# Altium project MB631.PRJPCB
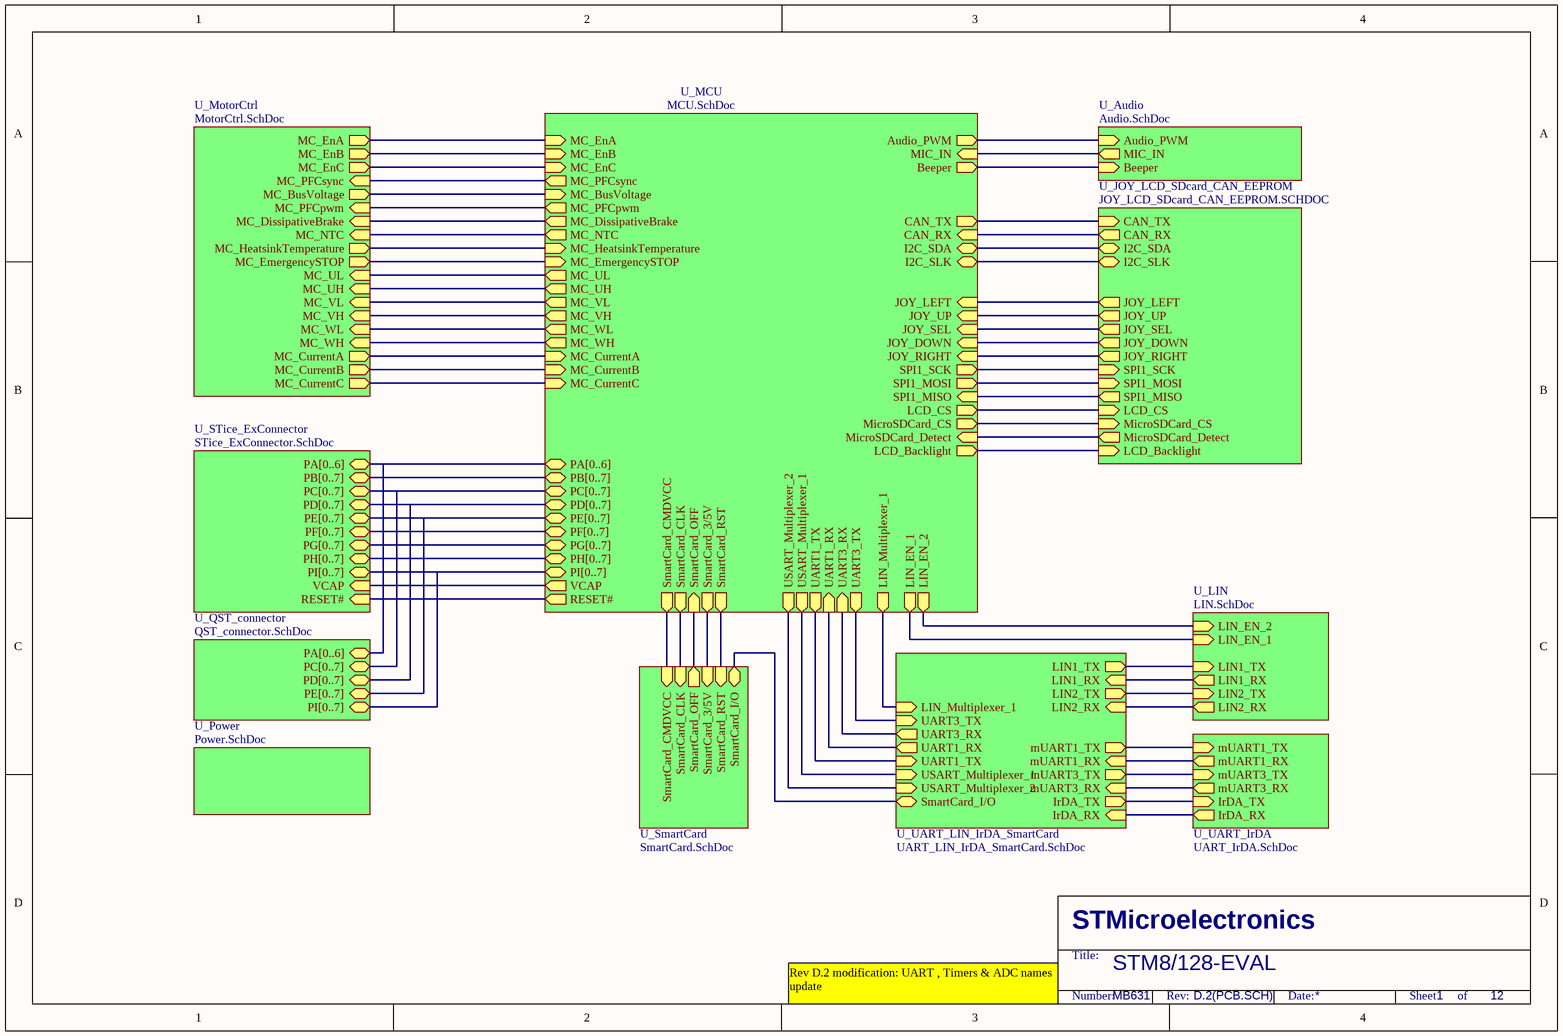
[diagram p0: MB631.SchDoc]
12 sheets, 273 parts. Net scope: hierarchical (ports join the sheet entries above them; power ports are global).
Board file: MB631.PCBDOC
Sheets:
  MB631.SchDoc
    U_MCU = MCU.SchDoc
    U_Audio = Audio.SchDoc
    U_MotorCtrl = MotorCtrl.SchDoc
    U_JOY_LCD_SDcard_CAN_EEPROM = JOY_LCD_SDcard_CAN_EEPROM.SCHDOC
    U_Power = Power.SchDoc
    U_STice_ExConnector = STice_ExConnector.SchDoc
    U_QST_connector = QST_connector.SchDoc
    U_LIN = LIN.SchDoc
    U_UART_IrDA = UART_IrDA.SchDoc
    U_UART_LIN_IrDA_SmartCard = UART_LIN_IrDA_SmartCard.SchDoc
    U_SmartCard = SmartCard.SchDoc

## Sheet MB631.SchDoc
size A4; Revision: D.2(PCB.SCH)

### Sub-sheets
U_Audio = Audio.SchDoc: Audio_PWM (in), MIC_IN (out), Beeper (in)
U_JOY_LCD_SDcard_CAN_EEPROM = JOY_LCD_SDcard_CAN_EEPROM.SCHDOC: JOY_SEL (out), JOY_DOWN (out), JOY_LEFT (out), JOY_RIGHT (out), JOY_UP (out), CAN_TX (in), CAN_RX (out), SPI1_SCK (in), SPI1_MISO (out), SPI1_MOSI (in), MicroSDCard_CS (in), LCD_CS (in), I2C_SLK (bidir), I2C_SDA (bidir), MicroSDCard_Detect (out), LCD_Backlight (in)
U_LIN = LIN.SchDoc: LIN_EN_1 (in), LIN1_TX (in), LIN1_RX (out), LIN_EN_2 (in), LIN2_TX (in), LIN2_RX (out)
U_MCU = MCU.SchDoc: MC_EnA (in), MC_EnB (in), MC_BusVoltage (in), SPI1_SCK (out), SPI1_MISO (in), SPI1_MOSI (out), MC_PFCsync (out), MC_PFCpwm (out), Audio_PWM (out), SmartCard_RST (out), SmartCard_CLK (out), MC_EnC (in), JOY_DOWN (in), MC_DissipativeBrake (out), JOY_SEL (in), SmartCard_3/5V (out), MC_NTC (out), JOY_UP (in), CAN_TX (out), CAN_RX (in), MC_EmergencySTOP (in), SmartCard_OFF (in), MC_WL (out), MC_VH (out), MC_VL (out), MC_UH (out), MC_UL (out), SmartCard_CMDVCC (out), JOY_LEFT (in), JOY_RIGHT (in), MC_WH (out), LCD_CS (out), MicroSDCard_CS (out), MC_CurrentC (in), MC_CurrentB (in), MC_CurrentA (in), MC_HeatsinkTemperature (in), MIC_IN (in), UART1_TX (out), UART1_RX (in), UART3_TX (out), UART3_RX (in), I2C_SLK (bidir), I2C_SDA (bidir), USART_Multiplexer_1 (out), USART_Multiplexer_2 (out), LIN_Multiplexer_1 (out), LIN_EN_1 (out), LIN_EN_2 (out), MicroSDCard_Detect (in), LCD_Backlight (out), Beeper (out), PA[0..6] (bidir), PB[0..7] (bidir), PC[0..7] (bidir), PD[0..7] (bidir), PE[0..7] (bidir), PF[0..7] (bidir), PG[0..7] (bidir), PH[0..7] (bidir), PI[0..7] (bidir), VCAP (out), RESET# (out)
U_MotorCtrl = MotorCtrl.SchDoc: MC_EmergencySTOP (out), MC_CurrentA (out), MC_CurrentB (out), MC_CurrentC (out), MC_PFCsync (in), MC_WL (in), MC_VH (in), MC_VL (in), MC_UH (in), MC_UL (in), MC_WH (in), MC_NTC (in), MC_DissipativeBrake (in), MC_PFCpwm (in), MC_EnA (out), MC_EnB (out), MC_HeatsinkTemperature (out), MC_BusVoltage (out), MC_EnC (out)
U_Power = Power.SchDoc: no entries
U_QST_connector = QST_connector.SchDoc: PA[0..6] (bidir), PC[0..7] (bidir), PD[0..7] (bidir), PE[0..7] (bidir), PI[0..7] (bidir)
U_SmartCard = SmartCard.SchDoc: SmartCard_3/5V (in), SmartCard_RST (in), SmartCard_CLK (in), SmartCard_OFF (out), SmartCard_CMDVCC (in), SmartCard_I/O (bidir)
U_STice_ExConnector = STice_ExConnector.SchDoc: PA[0..6] (bidir), PB[0..7] (bidir), PC[0..7] (bidir), PD[0..7] (bidir), PE[0..7] (bidir), PF[0..7] (bidir), PG[0..7] (bidir), PH[0..7] (bidir), PI[0..7] (bidir), VCAP (in), RESET# (in)
U_UART_IrDA = UART_IrDA.SchDoc: IrDA_TX (in), IrDA_RX (out), mUART1_TX (in), mUART1_RX (out), mUART3_TX (in), mUART3_RX (out)
U_UART_LIN_IrDA_SmartCard = UART_LIN_IrDA_SmartCard.SchDoc: USART_Multiplexer_1 (in), USART_Multiplexer_2 (in), LIN_Multiplexer_1 (in), UART1_TX (in), UART1_RX (out), UART3_TX (in), UART3_RX (out), LIN1_TX (out), LIN1_RX (in), IrDA_TX (out), IrDA_RX (in), SmartCard_I/O (bidir), mUART1_TX (out), mUART1_RX (in), LIN2_TX (out), LIN2_RX (in), mUART3_TX (out), mUART3_RX (in)

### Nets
PA3: sheet U_MCU/MC_EnC, sheet U_MotorCtrl/MC_EnC
PA4: sheet U_MCU/UART1_RX, sheet U_UART_LIN_IrDA_SmartCard/UART1_RX
PA5: sheet U_MCU/UART1_TX, sheet U_UART_LIN_IrDA_SmartCard/UART1_TX
PA6: sheet U_MCU/SmartCard_CLK, sheet U_SmartCard/SmartCard_CLK
PB0: sheet U_MCU/MC_CurrentC, sheet U_MotorCtrl/MC_CurrentC
PB1: sheet U_MCU/MC_CurrentB, sheet U_MotorCtrl/MC_CurrentB
PB2: sheet U_MCU/MC_CurrentA, sheet U_MotorCtrl/MC_CurrentA
PB3: sheet U_MCU/MC_BusVoltage, sheet U_MotorCtrl/MC_BusVoltage
PB4: sheet U_MCU/JOY_LEFT, sheet U_JOY_LCD_SDcard_CAN_EEPROM/JOY_LEFT
PB5: sheet U_MCU/JOY_RIGHT, sheet U_JOY_LCD_SDcard_CAN_EEPROM/JOY_RIGHT
PB6: sheet U_MCU/JOY_UP, sheet U_JOY_LCD_SDcard_CAN_EEPROM/JOY_UP
PB7: sheet U_MCU/JOY_DOWN, sheet U_JOY_LCD_SDcard_CAN_EEPROM/JOY_DOWN
PC1: sheet U_MCU/MC_UH, sheet U_MotorCtrl/MC_UH
PC2: sheet U_MCU/MC_VH, sheet U_MotorCtrl/MC_VH
PC3: sheet U_MCU/MC_WH, sheet U_MotorCtrl/MC_WH
PC4: sheet U_MCU/Audio_PWM, sheet U_Audio/Audio_PWM
PC5: sheet U_MCU/SPI1_SCK, sheet U_JOY_LCD_SDcard_CAN_EEPROM/SPI1_SCK
PC6: sheet U_MCU/SPI1_MOSI, sheet U_JOY_LCD_SDcard_CAN_EEPROM/SPI1_MOSI
PC7: sheet U_MCU/SPI1_MISO, sheet U_JOY_LCD_SDcard_CAN_EEPROM/SPI1_MISO
PD2: sheet U_MCU/MC_PFCsync, sheet U_MotorCtrl/MC_PFCsync
PD3: sheet U_MCU/MC_EnA, sheet U_MotorCtrl/MC_EnA
PD4: sheet U_MCU/MC_EnB, sheet U_MCU/Beeper, sheet U_Audio/Beeper, sheet U_MotorCtrl/MC_EnB
PD5: sheet U_MCU/UART3_TX, sheet U_UART_LIN_IrDA_SmartCard/UART3_TX
PD6: sheet U_MCU/UART3_RX, sheet U_UART_LIN_IrDA_SmartCard/UART3_RX
PD7: sheet U_MCU/JOY_SEL, sheet U_JOY_LCD_SDcard_CAN_EEPROM/JOY_SEL
PE0: sheet U_MCU/SmartCard_OFF, sheet U_SmartCard/SmartCard_OFF
PE1: sheet U_MCU/I2C_SLK, sheet U_JOY_LCD_SDcard_CAN_EEPROM/I2C_SLK
PE2: sheet U_MCU/I2C_SDA, sheet U_JOY_LCD_SDcard_CAN_EEPROM/I2C_SDA
PE3: sheet U_MCU/MC_EmergencySTOP, sheet U_MotorCtrl/MC_EmergencySTOP
PE5: sheet U_MCU/MicroSDCard_CS, sheet U_JOY_LCD_SDcard_CAN_EEPROM/MicroSDCard_CS
PE7: sheet U_MCU/MC_HeatsinkTemperature, sheet U_MotorCtrl/MC_HeatsinkTemperature
PF0: sheet U_MCU/LCD_CS, sheet U_JOY_LCD_SDcard_CAN_EEPROM/LCD_CS
PF3: sheet U_MCU/MIC_IN, sheet U_Audio/MIC_IN
PF5: sheet U_MCU/USART_Multiplexer_1, sheet U_UART_LIN_IrDA_SmartCard/USART_Multiplexer_1
PF6: sheet U_MCU/USART_Multiplexer_2, sheet U_UART_LIN_IrDA_SmartCard/USART_Multiplexer_2
PF7: sheet U_MCU/LIN_EN_1, sheet U_LIN/LIN_EN_1
PG0: sheet U_MCU/CAN_TX, sheet U_JOY_LCD_SDcard_CAN_EEPROM/CAN_TX
PG1: sheet U_MCU/CAN_RX, sheet U_JOY_LCD_SDcard_CAN_EEPROM/CAN_RX
PG2: sheet U_MCU/MC_NTC, sheet U_MotorCtrl/MC_NTC
PG3: sheet U_MCU/LIN_EN_2, sheet U_LIN/LIN_EN_2
PG4: sheet U_MCU/SmartCard_3/5V, sheet U_SmartCard/SmartCard_3/5V
PG5: sheet U_MCU/SmartCard_RST, sheet U_SmartCard/SmartCard_RST
PG6: sheet U_MCU/LIN_Multiplexer_1, sheet U_UART_LIN_IrDA_SmartCard/LIN_Multiplexer_1
PG7: sheet U_MCU/SmartCard_CMDVCC, sheet U_SmartCard/SmartCard_CMDVCC
PH4: sheet U_MCU/LCD_Backlight, sheet U_JOY_LCD_SDcard_CAN_EEPROM/LCD_Backlight
PH5: sheet U_MCU/MC_WL, sheet U_MotorCtrl/MC_WL
PH6: sheet U_MCU/MC_VL, sheet U_MotorCtrl/MC_VL
PH7: sheet U_MCU/MC_UL, sheet U_MotorCtrl/MC_UL
RESET#: sheet U_MCU/RESET#, sheet U_STice_ExConnector/RESET#
VCAP: sheet U_MCU/VCAP, sheet U_STice_ExConnector/VCAP
NetC39_2: sheet U_MCU/MC_PFCpwm, sheet U_MotorCtrl/MC_PFCpwm
NetCN9_10: sheet U_MCU/MicroSDCard_Detect, sheet U_JOY_LCD_SDcard_CAN_EEPROM/MicroSDCard_Detect
NetCN10_23: sheet U_MCU/MC_DissipativeBrake, sheet U_MotorCtrl/MC_DissipativeBrake
NetU14_3: sheet U_UART_IrDA/IrDA_TX, sheet U_UART_LIN_IrDA_SmartCard/IrDA_TX
NetU14_4: sheet U_UART_IrDA/IrDA_RX, sheet U_UART_LIN_IrDA_SmartCard/IrDA_RX
NetU15_1: sheet U_LIN/LIN1_RX, sheet U_UART_LIN_IrDA_SmartCard/LIN1_RX
NetU15_4: sheet U_LIN/LIN1_TX, sheet U_UART_LIN_IrDA_SmartCard/LIN1_TX
NetU16_1: sheet U_LIN/LIN2_RX, sheet U_UART_LIN_IrDA_SmartCard/LIN2_RX
NetU16_4: sheet U_LIN/LIN2_TX, sheet U_UART_LIN_IrDA_SmartCard/LIN2_TX
NetU17_4: sheet U_UART_IrDA/mUART1_RX, sheet U_UART_LIN_IrDA_SmartCard/mUART1_RX
NetU17_11: sheet U_UART_IrDA/mUART1_TX, sheet U_UART_LIN_IrDA_SmartCard/mUART1_TX
NetU17_15: sheet U_UART_LIN_IrDA_SmartCard/SmartCard_I/O, sheet U_SmartCard/SmartCard_I/O
NetU18_5: sheet U_UART_IrDA/mUART3_RX, sheet U_UART_LIN_IrDA_SmartCard/mUART3_RX
NetU18_14: sheet U_UART_IrDA/mUART3_TX, sheet U_UART_LIN_IrDA_SmartCard/mUART3_TX

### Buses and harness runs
bus sheet U_MCU/PA[0..6] = sheet U_QST_connector/PA[0..6] = sheet U_STice_ExConnector/PA[0..6]
bus sheet U_MCU/PB[0..7] = sheet U_STice_ExConnector/PB[0..7]
bus sheet U_MCU/PC[0..7] = sheet U_QST_connector/PC[0..7] = sheet U_STice_ExConnector/PC[0..7]
bus sheet U_MCU/PD[0..7] = sheet U_QST_connector/PD[0..7] = sheet U_STice_ExConnector/PD[0..7]
bus sheet U_MCU/PE[0..7] = sheet U_QST_connector/PE[0..7] = sheet U_STice_ExConnector/PE[0..7]
bus sheet U_MCU/PF[0..7] = sheet U_STice_ExConnector/PF[0..7]
bus sheet U_MCU/PG[0..7] = sheet U_STice_ExConnector/PG[0..7]
bus sheet U_MCU/PH[0..7] = sheet U_STice_ExConnector/PH[0..7]
bus sheet U_MCU/PI[0..7] = sheet U_QST_connector/PI[0..7] = sheet U_STice_ExConnector/PI[0..7]

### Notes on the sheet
- STM8/128-EVAL
- Rev D.2 modification: UART , Timers & ADC names update
- MB631
- 1
- 12

## Sheet MCU.SchDoc
size A4; Revision: D.2(PCB.SCH)
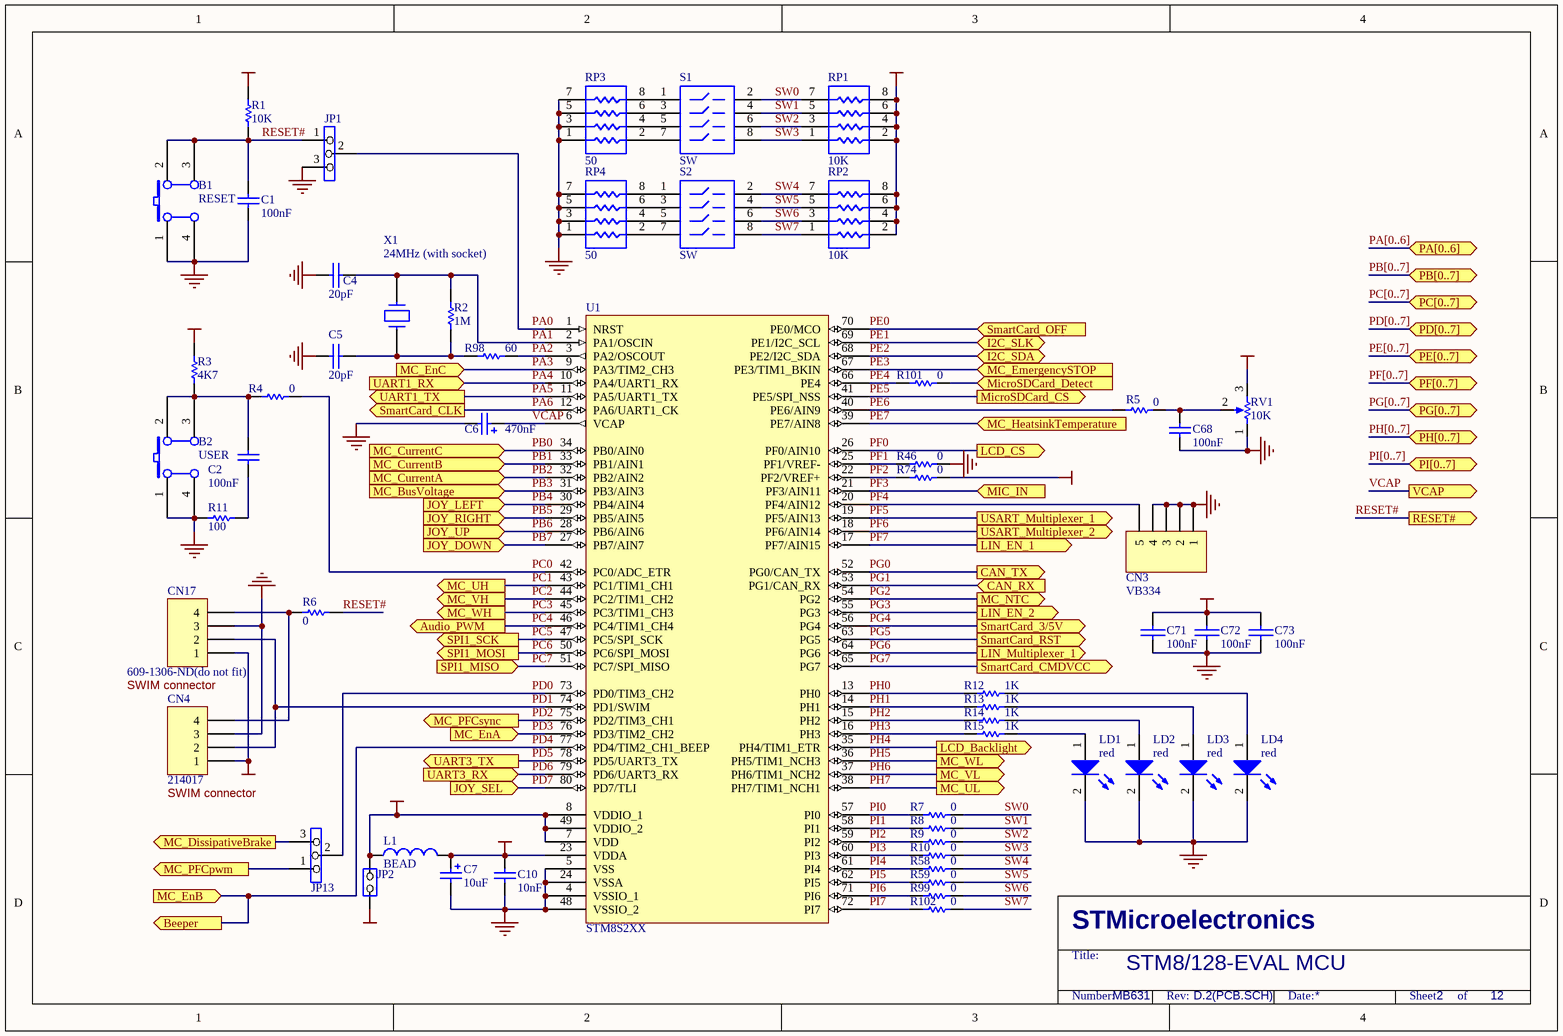
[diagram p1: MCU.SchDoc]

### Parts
B1  RESET  [PB10]
B2  USER  [PB10]
C1  100nF  [0603P]
C2  100nF  [0603P]
C4  20pF  [0603]
C5  20pF  [0603]
C6  470nF  [RB7.6-15]
C7  10uF  [TAN-B]
C10  10nF  [0603]
C68  100nF  [0603]
C71  100nF  [0603P]
C72  100nF  [0603P]
C73  100nF  [0603P]
CN3  VB334  [VB334]
CN4  214017  [214017]
CN17  609-1306-ND(do not fit)  [214012]
JP1  (no value)  [SIP3]
JP2  (no value)  [SIP2]
JP13  (no value)  [SIP3]
L1  BEAD  [0603]
LD1  red  [D0603]
LD2  red  [D0603]
LD3  red  [D0603]
LD4  red  [D0603]
R1  10K  [0603]
R2  1M  [0603]
R3  4K7  [0603]
R4  0  [0805]
R5  0  [0805]
R6  0  [0805]
R7  0  [0805]
R8  0  [0805]
R9  0  [0805]
R10  0  [0805]
R11  100  [0603]
R12  1K  [0805]
R13  1K  [0805]
R14  1K  [0805]
R15  1K  [0805]
R46  0  [0805]
R58  0  [0805]
R59  0  [0805]
R74  0  [0805]
R98  60  [0603]
R99  0  [0805]
R101  0  [0805]
R102  0  [0805]
RP1  10K
RP2  10K
RP3  50
RP4  50
RV1  10K  [ADJRH]
S1  SW  [DIP-8]
S2  SW  [DIP-8]
U1  STM8S2XX  [LQFP80]
X1  24MHz (with socket)  [XTAL1]

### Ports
Audio_PWM (out), Beeper (out), CAN_RX (in), CAN_TX (out), I2C_SDA (bidir), I2C_SLK (bidir), JOY_DOWN (in), JOY_LEFT (in), JOY_RIGHT (in), JOY_SEL (in), JOY_UP (in), LCD_Backlight (out), LCD_CS (out), LIN_EN_1 (out), LIN_EN_2 (out), LIN_Multiplexer_1 (out), MC_BusVoltage (in), MC_CurrentA (in), MC_CurrentB (in), MC_CurrentC (in), MC_DissipativeBrake (out), MC_EmergencySTOP (in), MC_EnA (in), MC_EnB (in), MC_EnC (in), MC_HeatsinkTemperature (in), MC_NTC (out), MC_PFCpwm (out), MC_PFCsync (out), MC_UH (out), MC_UL (out), MC_VH (out), MC_VL (out), MC_WH (out), MC_WL (out), MIC_IN (in), MicroSDCard_CS (out), MicroSDCard_Detect (in), PA[0..6] (bidir), PB[0..7] (bidir), PC[0..7] (bidir), PD[0..7] (bidir), PE[0..7] (bidir), PF[0..7] (bidir), PG[0..7] (bidir), PH[0..7] (bidir), PI[0..7] (bidir), RESET# (out), SmartCard_3/5V (out), SmartCard_CLK (out), SmartCard_CMDVCC (out), SmartCard_OFF (in), SmartCard_RST (out), SPI1_MISO (in), SPI1_MOSI (out), SPI1_SCK (out), UART1_RX (in), UART1_TX (out), UART3_RX (in), UART3_TX (out), USART_Multiplexer_1 (out), USART_Multiplexer_2 (out), VCAP (out)

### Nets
+5V: CN4.1 CN17.1 JP2.2(NO) R1.2 R3.2 RP1.2 RP1.4 RP1.6 RP1.8 RP2.2 RP2.4 RP2.6 RP2.8 RV1.3(TOP)
+5V_MCU: C71.1 C72.1 C73.1 JP2.1(COMMON) L1.1 U1.7(VDD) U1.8(VDDIO_1) U1.49(VDDIO_2)
+5V_VDDA: C7.1 C10.1 L1.2 R74.2 U1.23(VDDA)
GND: B1.1(A0) B1.4(A1) B2.1(A0) B2.4(A1) C1.1 C4.2 C5.2 C6.2 C7.2 C10.2 C68.2 C71.2 C72.2 C73.2 CN3.1 CN3.2 CN3.3 CN3.4 CN4.3 CN17.3 JP1.3 LD1.2(K) LD2.2(K) LD3.2(K) LD4.2(K) R11.1 R46.1 RP3.1 RP3.3 RP3.5 RP3.7 RP4.1 RP4.3 RP4.5 RP4.7 RV1.1(BOT) U1.4(VSSIO_1) U1.5(VSS) U1.24(VSSA) U1.48(VSSIO_2)
PA0: JP1.2 U1.1(NRST)
PA1: C4.1 R2.2 U1.2(PA1/OSCIN) X1.2
PA2: R98.1 U1.3(PA2/OSCOUT)
PA3: U1.9(PA3/TIM2_CH3) ; port MC_EnC
PA4: U1.10(PA4/UART1_RX) ; port UART1_RX
PA5: U1.11(PA5/UART1_TX) ; port UART1_TX
PA6: U1.12(PA6/UART1_CK) ; port SmartCard_CLK
PB0: U1.34(PB0/AIN0) ; port MC_CurrentC
PB1: U1.33(PB1/AIN1) ; port MC_CurrentB
PB2: U1.32(PB2/AIN2) ; port MC_CurrentA
PB3: U1.31(PB3/AIN3) ; port MC_BusVoltage
PB4: U1.30(PB4/AIN4) ; port JOY_LEFT
PB5: U1.29(PB5/AIN5) ; port JOY_RIGHT
PB6: U1.28(PB6/AIN6) ; port JOY_UP
PB7: U1.27(PB7/AIN7) ; port JOY_DOWN
PC0: R4.1 U1.42(PC0/ADC_ETR)
PC1: U1.43(PC1/TIM1_CH1) ; port MC_UH
PC2: U1.44(PC2/TIM1_CH2) ; port MC_VH
PC3: U1.45(PC3/TIM1_CH3) ; port MC_WH
PC4: U1.46(PC4/TIM1_CH4) ; port Audio_PWM
PC5: U1.47(PC5/SPI_SCK) ; port SPI1_SCK
PC6: U1.50(PC6/SPI_MOSI) ; port SPI1_MOSI
PC7: U1.51(PC7/SPI_MISO) ; port SPI1_MISO
PD0: JP13.2 U1.73(PD0/TIM3_CH2)
PD1: CN4.2 CN17.2 U1.74(PD1/SWIM)
PD2: U1.75(PD2/TIM3_CH1) ; port MC_PFCsync
PD3: U1.76(PD3/TIM2_CH2) ; port MC_EnA
PD4: U1.77(PD4/TIM2_CH1_BEEP) ; port MC_EnB, port Beeper
PD5: U1.78(PD5/UART3_TX) ; port UART3_TX
PD6: U1.79(PD6/UART3_RX) ; port UART3_RX
PD7: U1.80(PD7/TLI) ; port JOY_SEL
PE0: U1.70(PE0/MCO) ; port SmartCard_OFF
PE1: U1.69(PE1/I2C_SCL) ; port I2C_SLK
PE2: U1.68(PE2/I2C_SDA) ; port I2C_SDA
PE3: U1.67(PE3/TIM1_BKIN) ; port MC_EmergencySTOP
PE4: R101.2 U1.66(PE4)
PE5: U1.41(PE5/SPI_NSS) ; port MicroSDCard_CS
PE6: R5.1 U1.40(PE6/AIN9)
PE7: U1.39(PE7/AIN8) ; port MC_HeatsinkTemperature
PF0: U1.26(PF0/AIN10) ; port LCD_CS
PF1: R46.2 U1.25(PF1/VREF-)
PF2: R74.1 U1.22(PF2/VREF+)
PF3: U1.21(PF3/AIN11) ; port MIC_IN
PF4: CN3.5 U1.20(PF4/AIN12)
PF5: U1.19(PF5/AIN13) ; port USART_Multiplexer_1
PF6: U1.18(PF6/AIN14) ; port USART_Multiplexer_2
PF7: U1.17(PF7/AIN15) ; port LIN_EN_1
PG0: U1.52(PG0/CAN_TX) ; port CAN_TX
PG1: U1.53(PG1/CAN_RX) ; port CAN_RX
PG2: U1.54(PG2) ; port MC_NTC
PG3: U1.55(PG3) ; port LIN_EN_2
PG4: U1.56(PG4) ; port SmartCard_3/5V
PG5: U1.63(PG5) ; port SmartCard_RST
PG6: U1.64(PG6) ; port LIN_Multiplexer_1
PG7: U1.65(PG7) ; port SmartCard_CMDVCC
PH0: R12.2 U1.13(PH0)
PH1: R13.2 U1.14(PH1)
PH2: R14.2 U1.15(PH2)
PH3: R15.2 U1.16(PH3)
PH4: U1.35(PH4/TIM1_ETR) ; port LCD_Backlight
PH5: U1.36(PH5/TIM1_NCH3) ; port MC_WL
PH6: U1.37(PH6/TIM1_NCH2) ; port MC_VL
PH7: U1.38(PH7/TIM1_NCH1) ; port MC_UL
PI0: R7.2 U1.57(PI0)
PI1: R8.2 U1.58(PI1)
PI2: R9.2 U1.59(PI2)
PI3: R10.2 U1.60(PI3)
PI4: R58.2 U1.61(PI4)
PI5: R59.2 U1.62(PI5)
PI6: R99.2 U1.71(PI6)
PI7: R102.2 U1.72(PI7)
RESET#: B1.2(B0) B1.3(B1) C1.2 JP1.1 R1.1 R6.1 ; port RESET#
SW0: R7.1 RP1.7 S1.2
SW1: R8.1 RP1.5 S1.4
SW2: R9.1 RP1.3 S1.6
SW3: R10.1 RP1.1 S1.8
SW4: R58.1 RP2.7 S2.2
SW5: R59.1 RP2.5 S2.4
SW6: R99.1 RP2.3 S2.6
SW7: R102.1 RP2.1 S2.8
VCAP: C6.1 U1.6(VCAP) ; port VCAP
NetB2_2: B2.2(B0) B2.3(B1) C2.2 R3.1 R4.2
NetC2_1: C2.1 R11.2
NetC5_1: C5.1 R2.1 R98.2 X1.1
NetC39_2: JP13.1 ; port MC_PFCpwm
NetC68_1: C68.1 R5.2 RV1.2(TAP)
NetCN4_4: CN4.4 CN17.4 R6.2
NetCN9_10: R101.1 ; port MicroSDCard_Detect
NetCN10_23: JP13.3 ; port MC_DissipativeBrake
NetLD1_1: LD1.1(A) R15.1
NetLD2_1: LD2.1(A) R14.1
NetLD3_1: LD3.1(A) R13.1
NetLD4_1: LD4.1(A) R12.1
NetRP3_2: RP3.2 S1.7
NetRP3_4: RP3.4 S1.5
NetRP3_6: RP3.6 S1.3
NetRP3_8: RP3.8 S1.1
NetRP4_2: RP4.2 S2.7
NetRP4_4: RP4.4 S2.5
NetRP4_6: RP4.6 S2.3
NetRP4_8: RP4.8 S2.1

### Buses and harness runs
bus PA[0..6] = port PA[0..6]
bus PB[0..7] = port PB[0..7]
bus PC[0..7] = port PC[0..7]
bus PD[0..7] = port PD[0..7]
bus PE[0..7] = port PE[0..7]
bus PF[0..7] = port PF[0..7]
bus PG[0..7] = port PG[0..7]
bus PH[0..7] = port PH[0..7]
bus PI[0..7] = port PI[0..7]

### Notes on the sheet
- SWIM connector
- (near CN4) SWIM connector
- STM8/128-EVAL MCU
- MB631
- 2
- 12

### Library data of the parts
B1 B2 = SW PUSHBUTTON: SE PUSHBUTTON
C1 C2 = CAP: Capacitor; Value: 100pF
C4 C5 = CAP: Capacitor
C6 = Cap Pol1: Polarized Capacitor (Radial); Value: 100pF
C7 = Cap Pol1: Polarized Capacitor (Radial)
C10 = Cap: Capacitor
C68 = Cap: Capacitor; Value: 10nF
C71-C73 = CAP
CN3 = Header 5: Header, 5-Pin
CN4 CN17 = Header 4: Header, 4-Pin
JP1 JP13 = Jumper3
JP2 = JP2
L1 = Inductor: Value: 100uH
LD1-LD4 = LED2: Typical RED, GREEN, YELLOW, AMBER GaAs LED
R1 R3 = res1: Resistor; Value: 1K
R2 R4-R11 R46 R58 R59 R74 R98 R99 R101 R102 = Res1: Resistor; Value: 1K
R12-R15 = Res1: Resistor
RP1-RP4 = RP4
RV1 = RV
S1 S2 = SW-DIP4: DIP Switch
X1 = CRYSTAL

## Sheet Audio.SchDoc
size A4; Revision: D.2(PCB.SCH)
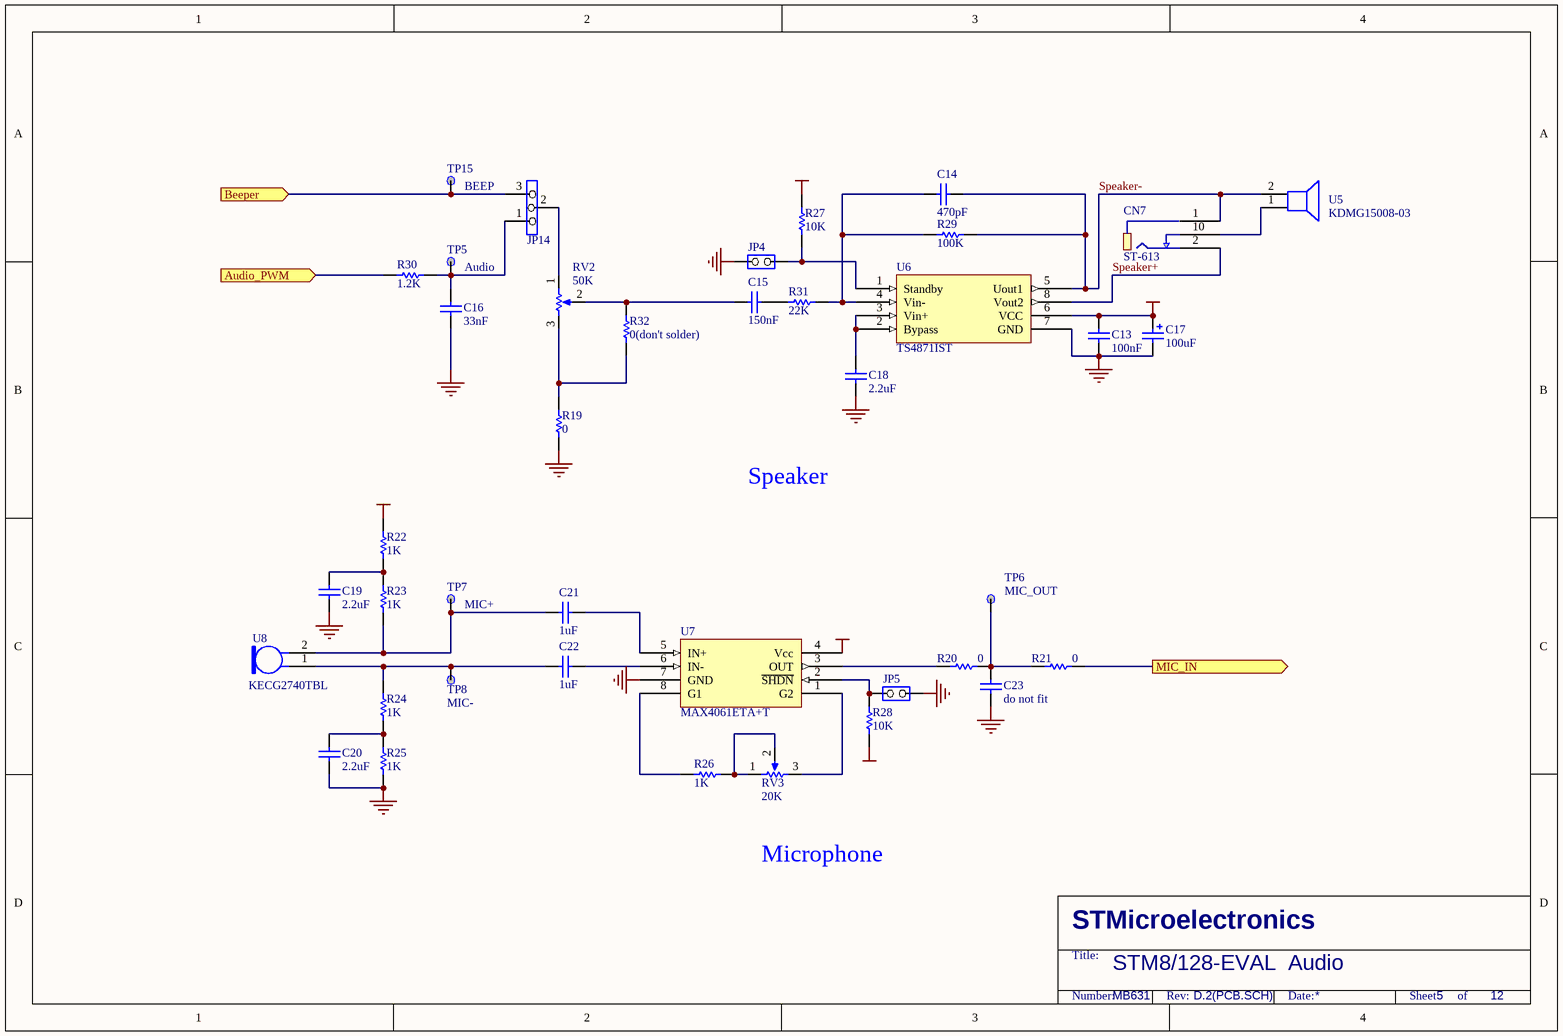
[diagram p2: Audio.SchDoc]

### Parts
C13  100nF  [0603P]
C14  470pF  [0603]
C15  150nF  [0603]
C16  33nF  [0603]
C17  100uF  [TAN-B]
C18  2.2uF  [0805]
C19  2.2uF  [0805]
C20  2.2uF  [0805]
C21  1uF  [0603]
C22  1uF  [0603]
C23  do not fit  [0603]
CN7  ST-613  [PJST-613]
JP4  (no value)  [SIP2]
JP5  (no value)  [SIP2]
JP14  (no value)  [SIP3]
R19  0  [0603]
R20  0  [0603]
R21  0  [0805]
R22  1K  [0603]
R23  1K  [0603]
R24  1K  [0603]
R25  1K  [0603]
R26  1K  [0603]
R27  10K  [0603]
R28  10K  [0603]
R29  100K  [0603]
R30  1.2K  [0603]
R31  22K  [0603]
R32  0(don't solder)  [0603]
RV2  50K  [3314-J]
RV3  20K  [3314-J]
TP5  Audio  [TP]
TP6  MIC_OUT  [TP]
TP7  MIC+  [TP]
TP8  MIC-  [TP]
TP15  BEEP  [TP]
U5  KDMG15008-03  [KS1508]
U6  TS4871IST  [TSSOP8]
U7  MAX4061ETA+T  [THIN QFN8]
U8  KECG2740TBL  [KEC2740]

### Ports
Audio_PWM (in), Beeper (in), MIC_IN (out)

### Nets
+5V: C13.2 C17.1 R22.2 R27.2 R28.1 U6.6(VCC) U7.4(Vcc)
GND: C13.1 C16.1 C17.2 C18.2 C19.2 C20.2 C23.2 JP4.2(NO) JP5.2(NO) R19.1 R25.1 U6.7(GND) U7.7(GND)
PC4: R30.1 ; port Audio_PWM
PD4: JP14.3 TP15.1 ; port Beeper
PF3: R21.1 ; port MIC_IN
Speaker+: CN7.2 U6.8(Vout2)
Speaker-: C14.2 CN7.1 R29.2 U5.2(--) U6.5(Uout1)
NetC14_1: C14.1 R29.1 R31.2 U6.4(Vin-)
NetC15_1: C15.1 R32.2 RV2.2(TAP)
NetC15_2: C15.2 R31.1
NetC16_2: C16.2 JP14.1 R30.2 TP5.1
NetC18_1: C18.1 U6.2(Bypass) U6.3(Vin+)
NetC19_1: C19.1 R22.1 R23.1
NetC20_1: C20.1 R24.1 R25.2
NetC21_1: C21.1 R23.2 TP7.1 U8.2
NetC21_2: C21.2 U7.5(IN+)
NetC22_1: C22.1 R24.2 TP8.1 U8.1
NetC22_2: C22.2 U7.6(IN-)
NetC23_1: C23.1 R20.1 R21.2 TP6.1
NetCN7_10: CN7.10 U5.1(+)
NetJP4_1: JP4.1(COMMON) R27.1 U6.1(Standby)
NetJP5_1: JP5.1(COMMON) R28.2 U7.2(~{SHDN})
NetJP14_2: JP14.2 RV2.1(BOT)
NetR19_2: R19.2 R32.1 RV2.3(TOP)
NetR20_2: R20.2 U7.3(OUT)
NetR26_1: R26.1 RV3.1(BOT) RV3.2(TAP)
NetR26_2: R26.2 U7.8(G1)
NetRV3_3: RV3.3(TOP) U7.1(G2)

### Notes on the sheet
- Speaker
- Microphone
- STM8/128-EVAL  Audio
- MB631
- 5
- 12

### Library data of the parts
C13-C16 C18-C22 = CAP: Capacitor; Value: 100pF
C17 = Cap Pol1: as C6 on sheet MCU
C23 = CAP: Capacitor; Value: 100nF
JP4 JP5 = JP2
JP14 = Jumper3
R19-R21 R27-R32 = Res1: Resistor; Value: 1K
R22-R26 = Res1: Resistor
RV2 RV3 = RV
TP5-TP8 TP15 = TP
U5 = Speaker: Loudspeaker
U7 = MAX4061EUA+
U8 = Mic2: Microphone

## Sheet MotorCtrl.SchDoc
size A4; Revision: D.2(PCB.SCH)
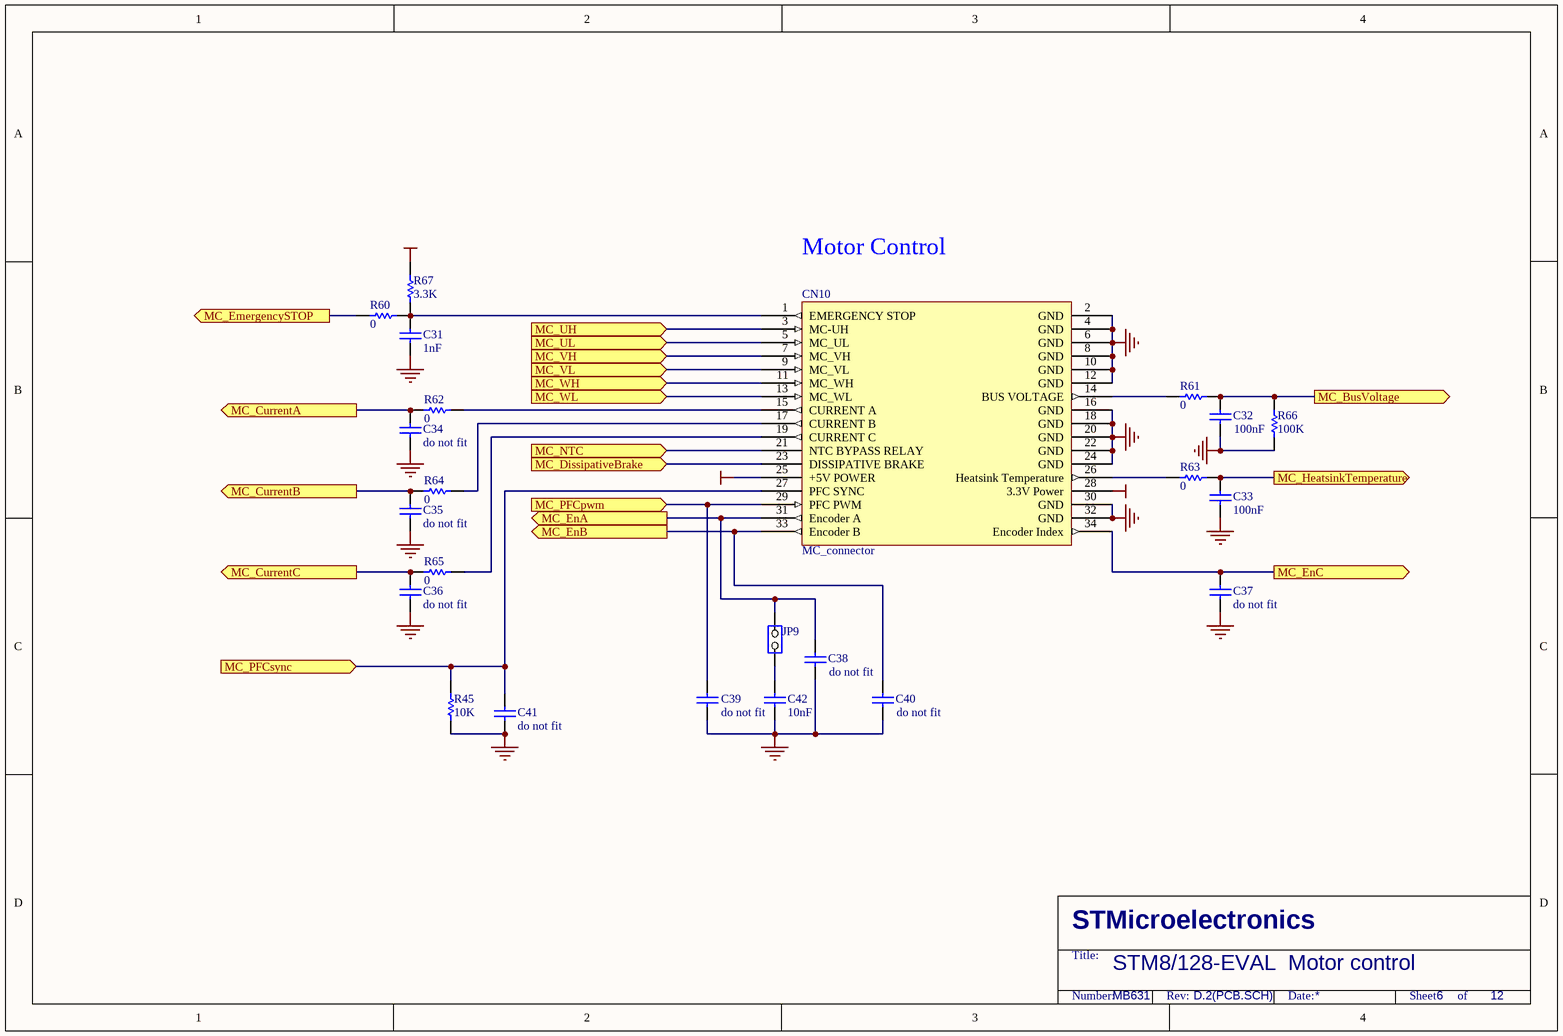
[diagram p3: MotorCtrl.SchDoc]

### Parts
C31  1nF  [0603]
C32  100nF  [0603]
C33  100nF  [0603]
C34  do not fit  [0603]
C35  do not fit  [0603]
C36  do not fit  [0603]
C37  do not fit  [0603]
C38  do not fit  [0603]
C39  do not fit  [0603]
C40  do not fit  [0603]
C41  do not fit  [0603]
C42  10nF  [0603]
CN10  MC_connector  [IDC34S]
JP9  (no value)  [SIP2]
R45  10K  [0603]
R60  0  [0805]
R61  0  [0603]
R62  0  [0603]
R63  0  [0603]
R64  0  [0603]
R65  0  [0603]
R66  100K  [0603]
R67  3.3K  [0603]

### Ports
MC_BusVoltage (out), MC_CurrentA (out), MC_CurrentB (out), MC_CurrentC (out), MC_DissipativeBrake (in), MC_EmergencySTOP (out), MC_EnA (out), MC_EnB (out), MC_EnC (out), MC_HeatsinkTemperature (out), MC_NTC (in), MC_PFCpwm (in), MC_PFCsync (in), MC_UH (in), MC_UL (in), MC_VH (in), MC_VL (in), MC_WH (in), MC_WL (in)

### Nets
+3V3: CN10.28(3.3V_Power)
+5V: CN10.25(+5V_POWER) R67.2
GND: C31.1 C32.1 C33.1 C34.1 C35.1 C36.1 C37.1 C38.1 C39.1 C40.1 C41.1 C42.1 CN10.2(GND) CN10.4(GND) CN10.6(GND) CN10.8(GND) CN10.10(GND) CN10.12(GND) CN10.16(GND) CN10.18(GND) CN10.20(GND) CN10.22(GND) CN10.24(GND) CN10.30(GND) CN10.32(GND) R45.1 R66.1
PA3: C37.2 CN10.34(Encoder_Index) ; port MC_EnC
PB0: C36.2 R65.1 ; port MC_CurrentC
PB1: C35.2 R64.1 ; port MC_CurrentB
PB2: C34.2 R62.1 ; port MC_CurrentA
PB3: C32.2 R61.2 R66.2 ; port MC_BusVoltage
PC1: CN10.3(MC-UH) ; port MC_UH
PC2: CN10.7(MC_VH) ; port MC_VH
PC3: CN10.11(MC_WH) ; port MC_WH
PD2: C41.2 CN10.27(PFC_SYNC) R45.2 ; port MC_PFCsync
PD3: C38.2 CN10.31(Encoder_A) JP9.1(COMMON) ; port MC_EnA
PD4: C40.2 CN10.33(Encoder_B) ; port MC_EnB
PE3: R60.2 ; port MC_EmergencySTOP
PE7: C33.2 R63.2 ; port MC_HeatsinkTemperature
PG2: CN10.21(NTC_BYPASS_RELAY) ; port MC_NTC
PH5: CN10.13(MC_WL) ; port MC_WL
PH6: CN10.9(MC_VL) ; port MC_VL
PH7: CN10.5(MC_UL) ; port MC_UL
NetC31_2: C31.2 CN10.1(EMERGENCY_STOP) R60.1 R67.1
NetC39_2: C39.2 CN10.29(PFC_PWM) ; port MC_PFCpwm
NetC42_2: C42.2 JP9.2(NO)
NetCN10_14: CN10.14(BUS_VOLTAGE) R61.1
NetCN10_15: CN10.15(CURRENT_A) R62.2
NetCN10_17: CN10.17(CURRENT_B) R64.2
NetCN10_19: CN10.19(CURRENT_C) R65.2
NetCN10_23: CN10.23(DISSIPATIVE_BRAKE) ; port MC_DissipativeBrake
NetCN10_26: CN10.26(Heatsink_Temperature) R63.1

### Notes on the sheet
- Motor Control
- STM8/128-EVAL  Motor control
- MB631
- 6
- 12

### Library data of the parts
C31 = CAP: Capacitor; Value: 100pF
C32-C42 = cap: Capacitor; Value: 100pF
JP9 = JP2
R45 R60-R67 = Res1: Resistor; Value: 1K

## Sheet JOY_LCD_SDcard_CAN_EEPROM.SCHDOC
size A4; Revision: D.2(PCB.SCH)
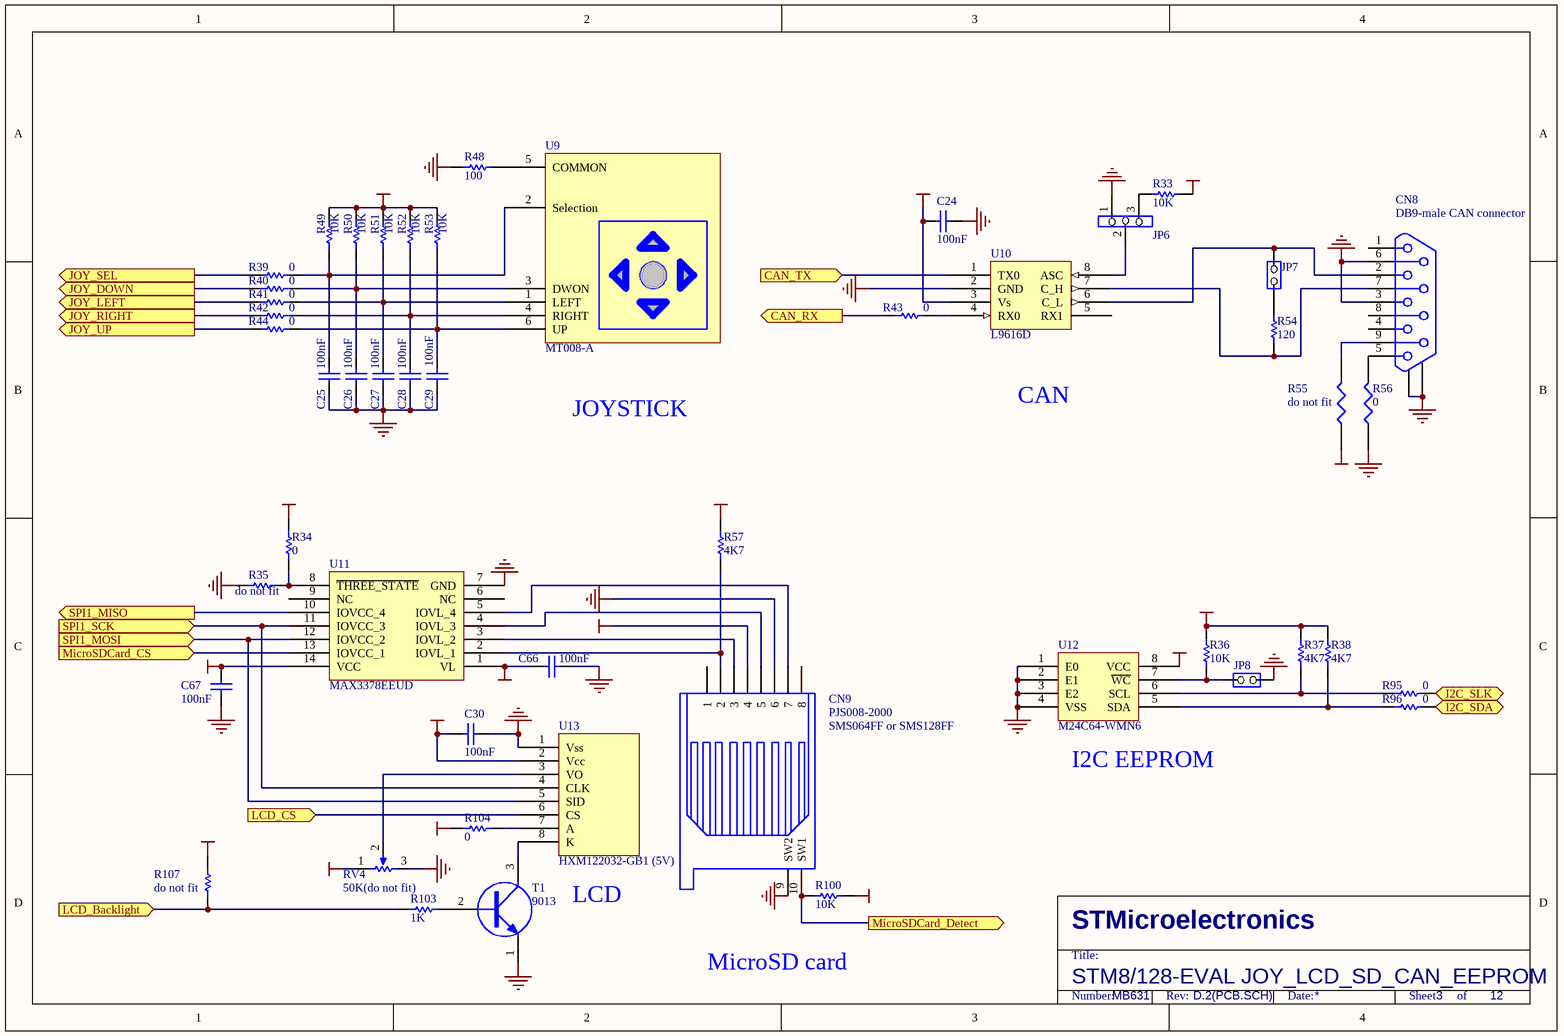
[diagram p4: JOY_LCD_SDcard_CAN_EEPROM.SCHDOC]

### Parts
C24  100nF  [0603P]
C25  100nF  [0603P]
C26  100nF  [0603P]
C27  100nF  [0603P]
C28  100nF  [0603P]
C29  100nF  [0603P]
C30  100nF  [0603P]
C66  100nF  [0603P]
C67  100nF  [0603P]
CN8  DB9-male CAN connector  [DB9/M]
CN9  PJS008-2000  [MSD(PJS008)]
JP6  (no value)  [SIP3]
JP7  (no value)  [SIP2]
JP8  (no value)  [SIP2]
R33  10K  [0603]
R34  0  [0805]
R35  do not fit  [0603]
R36  10K  [0603]
R37  4K7  [0603]
R38  4K7  [0603]
R39  0  [0805]
R40  0  [0805]
R41  0  [0805]
R42  0  [0805]
R43  0  [0805]
R44  0  [0805]
R48  100  [0603]
R49  10K  [0603]
R50  10K  [0603]
R51  10K  [0603]
R52  10K  [0603]
R53  10K  [0603]
R54  120  [0603]
R55  do not fit  [0603]
R56  0  [0603]
R57  4K7  [0603]
R95  0  [0805]
R96  0  [0805]
R100  10K  [0603]
R103  1K  [0603]
R104  0  [0603]
R107  do not fit  [0603]
RV4  50K(do not fit)  [3314-J]
T1  9013  [SOT-23]
U9  MT008-A  [JOY]
U10  L9616D  [SO-8]
U11  MAX3378EEUD  [TSSOP14]
U12  M24C64-WMN6  [SO8]
U13  HXM122032-GB1 (5V)  [LCD12232-GB1]

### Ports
CAN_RX (out), CAN_TX (in), I2C_SDA (bidir), I2C_SLK (bidir), JOY_DOWN (out), JOY_LEFT (out), JOY_RIGHT (out), JOY_SEL (out), JOY_UP (out), LCD_Backlight (in), LCD_CS (in), MicroSDCard_CS (in), MicroSDCard_Detect (out), SPI1_MISO (out), SPI1_MOSI (in), SPI1_SCK (in)

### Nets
+3V3: C66.2 CN9.4 R34.2 R55.1 R57.2 U11.1(VL)
+5V: C24.2 C30.1 C67.2 R33.2 R36.1 R37.1 R38.1 R49.1 R50.2 R51.2 R52.2 R53.2 R100.2 R104.1 R107.1 RV4.1(BOT) U10.3(Vs) U11.14(VCC) U12.8(VCC) U13.2(Vcc)
GND: C24.1 C25.1 C26.1 C27.1 C28.1 C29.1 C30.2 C66.1 C67.1 CN8.0 CN8.3 CN8.6 CN9.6 CN9.9(SW2) JP6.1 JP8.2(NO) R35.1 R48.1 R56.1 RV4.3(TOP) T1.1(E) U10.2(GND) U11.7(GND) U12.1(E0) U12.2(E1) U12.3(E2) U12.4(VSS) U13.1(Vss)
PB4: R41.2 ; port JOY_LEFT
PB5: R42.2 ; port JOY_RIGHT
PB6: R44.2 ; port JOY_UP
PB7: R40.2 ; port JOY_DOWN
PC5: U11.11(IOVCC_3) U13.4(CLK) ; port SPI1_SCK
PC6: U11.12(IOVCC_2) U13.5(SID) ; port SPI1_MOSI
PC7: U11.10(IOVCC_4) ; port SPI1_MISO
PD7: R39.2 ; port JOY_SEL
PE1: R95.1 ; port I2C_SLK
PE2: R96.1 ; port I2C_SDA
PE5: U11.13(IOVCC_1) ; port MicroSDCard_CS
PF0: U13.6(CS) ; port LCD_CS
PG0: U10.1(TX0) ; port CAN_TX
PG1: R43.2 ; port CAN_RX
PH4: R103.2 R107.2 ; port LCD_Backlight
NetC25_2: C25.2 R39.1 R49.2 U9.2(Selection)
NetC26_2: C26.2 R40.1 R50.1 U9.3(DWON)
NetC27_2: C27.2 R41.1 R51.1 U9.1(LEFT)
NetC28_2: C28.2 R42.1 R52.1 U9.4(RIGHT)
NetC29_2: C29.2 R44.1 R53.1 U9.6(UP)
NetCN8_2: CN8.2 JP7.2(NO) U10.6(C_L)
NetCN8_5: CN8.5 R56.2
NetCN8_7: CN8.7 R54.1 U10.7(C_H)
NetCN8_9: CN8.9 R55.2
NetCN9_2: CN9.2 R57.1 U11.2(IOVL_1)
NetCN9_3: CN9.3 U11.3(IOVL_2)
NetCN9_5: CN9.5 U11.4(IOVL_3)
NetCN9_7: CN9.7 U11.5(IOVL_4)
NetCN9_10: CN9.10(SW1) R100.1 ; port MicroSDCard_Detect
NetJP6_2: JP6.2 U10.8(ASC)
NetJP6_3: JP6.3 R33.1
NetJP7_1: JP7.1(COMMON) R54.2
NetJP8_1: JP8.1(COMMON) R36.2 U12.7(~{WC})
NetR34_1: R34.1 R35.2 U11.8(~{THREE_STATE})
NetR37_2: R37.2 R95.2 U12.6(SCL)
NetR38_2: R38.2 R96.2 U12.5(SDA)
NetR43_1: R43.1 U10.4(RX0)
NetR48_2: R48.2 U9.5(COMMON)
NetR103_1: R103.1 T1.2(B)
NetR104_2: R104.2 U13.7(A)
NetRV4_2: RV4.2(TAP) U13.3(VO)
NetT1_3: T1.3(C) U13.8(K)

Not connected (* = marked no-connect by the designer): CN8 1 4 8; CN9 1 8; U10 5(RX1); U11 6(NC) 9(NC)

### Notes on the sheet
- JOYSTICK
- CAN
- (near CN9) SMS064FF or SMS128FF
- (near U12) I2C EEPROM
- LCD
- MicroSD card
- STM8/128-EVAL JOY_LCD_SD_CAN_EEPROM
- MB631
- 3
- 12

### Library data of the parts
C24 = CAP: Capacitor
C25-C30 C66 C67 = CAP: Capacitor; Value: 100pF
CN8 = DB9
CN9 = SMS016AFA5E
JP6 = Jumper3
JP7 JP8 = JP2
R33-R38 R54 R100 = res1: Resistor; Value: 1K
R39-R44 R48-R53 R57 R95 R96 R104 R107 = Res1: Resistor; Value: 1K
R55 R56 = RES1
R103 = Res1: Resistor
RV4 = RV
T1 = NPN
U9 = MT-008A
U10 = L9616
U13 = HXM122032-GB1

## Sheet Power.SchDoc
size A4; Revision: D.2(PCB.SCH)
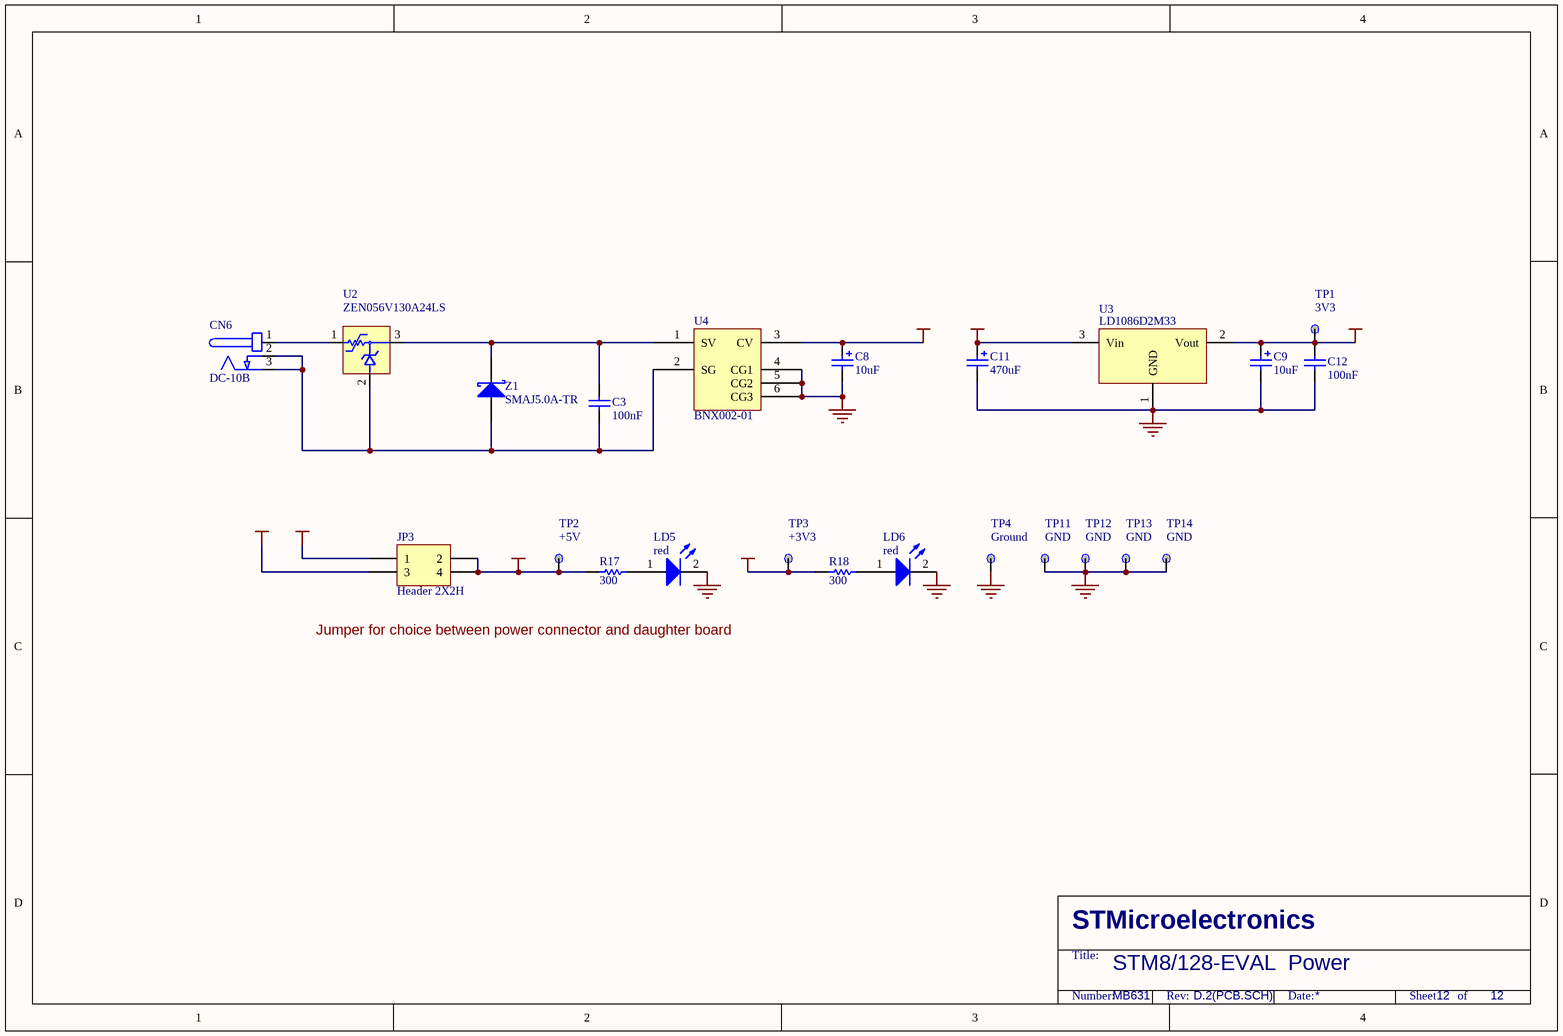
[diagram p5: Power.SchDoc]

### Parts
C3  100nF  [0603P]
C8  10uF  [C160M]
C9  10uF  [TAN-B]
C11  470uF  [C310M]
C12  100nF  [0603P]
CN6  DC-10B  [DC10B]
JP3  Header 2X2H  [HDR2X2H]
LD5  red  [D0603]
LD6  red  [D0603]
R17  300  [0603]
R18  300  [0603]
TP1  3V3  [TP]
TP2  +5V  [TP]
TP3  +3V3  [TP]
TP4  Ground  [TP]
TP11  GND  [TP]
TP12  GND  [TP]
TP13  GND  [TP]
TP14  GND  [TP]
U2  ZEN056V130A24LS  [polyzen]
U3  LD1086D2M33  [D2PAK/A]
U4  BNX002-01  [BNX001]
Z1  SMAJ5.0A-TR  [1R1C]

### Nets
+3V3: C9.1 C12.1 R18.2 TP1.1 TP3.1 U3.2(Vout)
+5V: C11.1 JP3.2 JP3.4 R17.2 TP2.1 U3.3(Vin)
D5V: JP3.1
E5V: C8.1 JP3.3 U4.3(CV)
GND: C8.2 C9.2 C11.2 C12.2 LD5.2(K) LD6.2(K) TP4.1 TP11.1 TP12.1 TP13.1 TP14.1 U3.1(GND) U4.4(CG1) U4.5(CG2) U4.6(CG3)
NetC3_1: C3.1 U2.3 U4.1(SV) Z1.2(K)
NetC3_2: C3.2 CN6.2(GND) CN6.3(GND) U2.2 U4.2(SG) Z1.1(A)
NetCN6_1: CN6.1(+) U2.1
NetLD5_1: LD5.1(A) R17.1
NetLD6_1: LD6.1(A) R18.1

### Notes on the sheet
- Jumper for choice between power connector and daughter board
- STM8/128-EVAL  Power
- MB631
- 12

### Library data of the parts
C3 = CAP: Capacitor; Value: 100pF
C8 = Cap Pol1: Polarized Capacitor (Radial); Value: 47uF
C9 = Cap Pol1: Polarized Capacitor (Radial)
C11 = Cap Pol1: Polarized Capacitor (Radial); Value: 10uF
C12 = Cap: Capacitor; Value: 10nF
CN6 = PJ202A
JP3 = Header 2X2H: Header, 2-Pin, Dual row, Right Angle
LD5 LD6 = LED2: as LD1 on sheet MCU
R17 R18 = res1: Resistor; Value: 1K
TP1-TP4 TP11-TP14 = TP
U3 = VOLTREG1
U4 = BNX002
Z1 = D Schottky: Schottky Diode; Code - JEDEC: DO-214-AA

## Sheet STice_ExConnector.SchDoc
size A4; Revision: D.2(PCB.SCH)
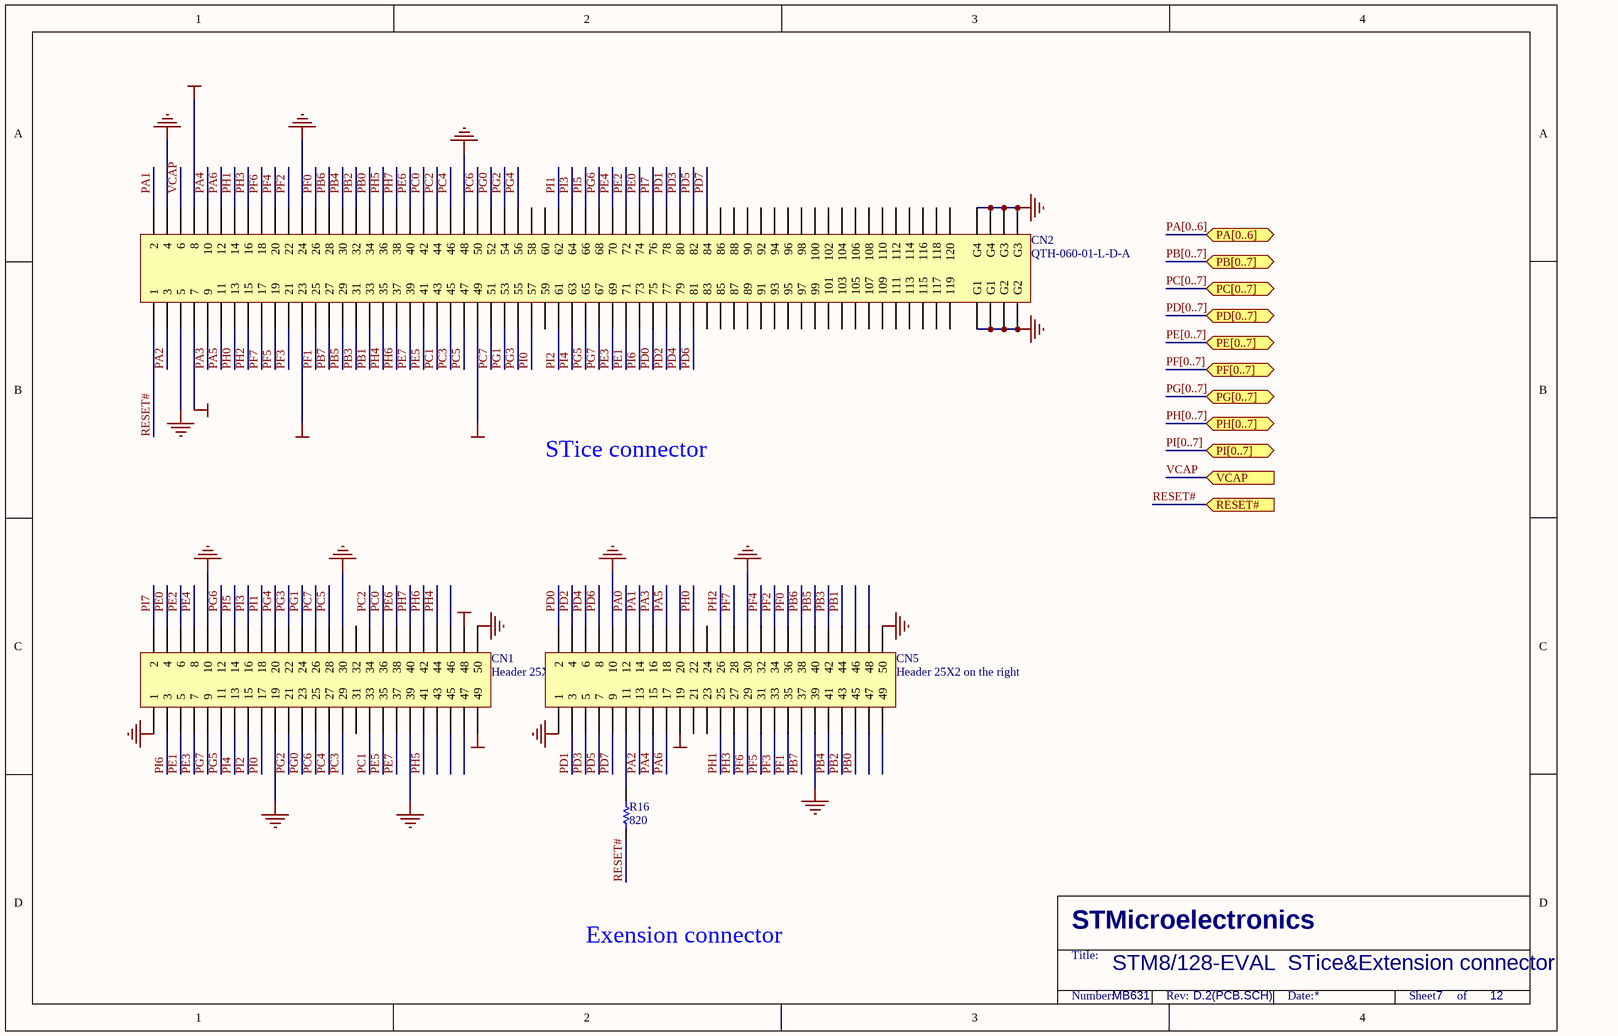
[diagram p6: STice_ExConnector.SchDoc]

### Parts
CN1  Header 25X2 on the left  [2*25P]
CN2  QTH-060-01-L-D-A  [QTH-060-01-L-D-A]
CN5  Header 25X2 on the right  [2*25P]
R16  820  [0603]

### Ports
PA[0..6] (bidir), PB[0..7] (bidir), PC[0..7] (bidir), PD[0..7] (bidir), PE[0..7] (bidir), PF[0..7] (bidir), PG[0..7] (bidir), PH[0..7] (bidir), PI[0..7] (bidir), RESET# (in), VCAP (in)

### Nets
+3V3: CN1.48
+5V_MCU: CN2.7 CN2.8 CN2.49
+5V_VDDA: CN2.23
D5V: CN1.49 CN5.19
GND: CN1.1 CN1.10 CN1.19 CN1.30 CN1.39 CN1.50 CN2.4 CN2.5 CN2.24 CN2.48 CN2.G1 CN2.G2 CN2.G3 CN2.G4 CN5.1 CN5.10 CN5.30 CN5.39 CN5.50
PA0: CN5.12
PA1: CN2.2 CN5.14
PA2: CN2.3 CN5.13
PA3: CN2.9 CN5.16
PA4: CN2.10 CN5.15
PA5: CN2.11 CN5.18
PA6: CN2.12 CN5.17
PB0: CN2.34 CN5.45
PB1: CN2.33 CN5.44
PB2: CN2.32 CN5.43
PB3: CN2.31 CN5.42
PB4: CN2.30 CN5.41
PB5: CN2.29 CN5.40
PB6: CN2.28 CN5.38
PB7: CN2.27 CN5.37
PC0: CN1.36 CN2.42
PC1: CN1.33 CN2.43
PC2: CN1.34 CN2.44
PC3: CN1.29 CN2.45
PC4: CN1.27 CN2.46
PC5: CN1.28 CN2.47
PC6: CN1.25 CN2.50
PC7: CN1.26 CN2.51
PD0: CN2.75 CN5.2
PD1: CN2.78 CN5.3
PD2: CN2.77 CN5.4
PD3: CN2.80 CN5.5
PD4: CN2.79 CN5.6
PD5: CN2.82 CN5.7
PD6: CN2.81 CN5.8
PD7: CN2.84 CN5.9
PE0: CN1.4 CN2.74
PE1: CN1.5 CN2.71
PE2: CN1.6 CN2.72
PE3: CN1.7 CN2.69
PE4: CN1.8 CN2.70
PE5: CN1.35 CN2.41
PE6: CN1.38 CN2.40
PE7: CN1.37 CN2.39
PF0: CN2.26 CN5.36
PF1: CN2.25 CN5.35
PF2: CN2.22 CN5.34
PF3: CN2.21 CN5.33
PF4: CN2.20 CN5.32
PF5: CN2.19 CN5.31
PF6: CN2.18 CN5.29
PF7: CN2.17 CN5.28
PG0: CN1.23 CN2.52
PG1: CN1.24 CN2.53
PG2: CN1.21 CN2.54
PG3: CN1.22 CN2.55
PG4: CN1.20 CN2.56
PG5: CN1.11 CN2.65
PG6: CN1.12 CN2.68
PG7: CN1.9 CN2.67
PH0: CN2.13 CN5.22
PH1: CN2.14 CN5.25
PH2: CN2.15 CN5.26
PH3: CN2.16 CN5.27
PH4: CN1.44 CN2.35
PH5: CN1.41 CN2.36
PH6: CN1.42 CN2.37
PH7: CN1.40 CN2.38
PI0: CN1.17 CN2.57
PI1: CN1.18 CN2.62
PI2: CN1.15 CN2.61
PI3: CN1.16 CN2.64
PI4: CN1.13 CN2.63
PI5: CN1.14 CN2.66
PI6: CN1.3 CN2.73
PI7: CN1.2 CN2.76
RESET#: CN2.1 R16.2 ; port RESET#
VCAP: CN2.6 ; port VCAP
NetCN5_11: CN5.11 R16.1

Not connected (* = marked no-connect by the designer): CN1 31 32 43 45 46 47; CN2 58 59 60 83 85 86 87 88 89 90 91 92 93 94 95 96 97 98 99 100 101 102 103 104 105 106 107 108 109 110 111 112 113 114 115 116 117 118 119 120; CN5 20 21 23 24 46 47 48 49

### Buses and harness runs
bus PA[0..6] = port PA[0..6]
bus PB[0..7] = port PB[0..7]
bus PC[0..7] = port PC[0..7]
bus PD[0..7] = port PD[0..7]
bus PE[0..7] = port PE[0..7]
bus PF[0..7] = port PF[0..7]
bus PG[0..7] = port PG[0..7]
bus PH[0..7] = port PH[0..7]
bus PI[0..7] = port PI[0..7]

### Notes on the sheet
- STice connector
- Exension connector
- STM8/128-EVAL  STice&Extension connector
- MB631
- 7
- 12

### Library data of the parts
CN1 CN5 = Header 25X2: Header, 25-Pin, Dual row
R16 = Res1: Resistor; Value: 1K

## Sheet QST_connector.SchDoc
size A4; Revision: D.2(PCB.SCH)
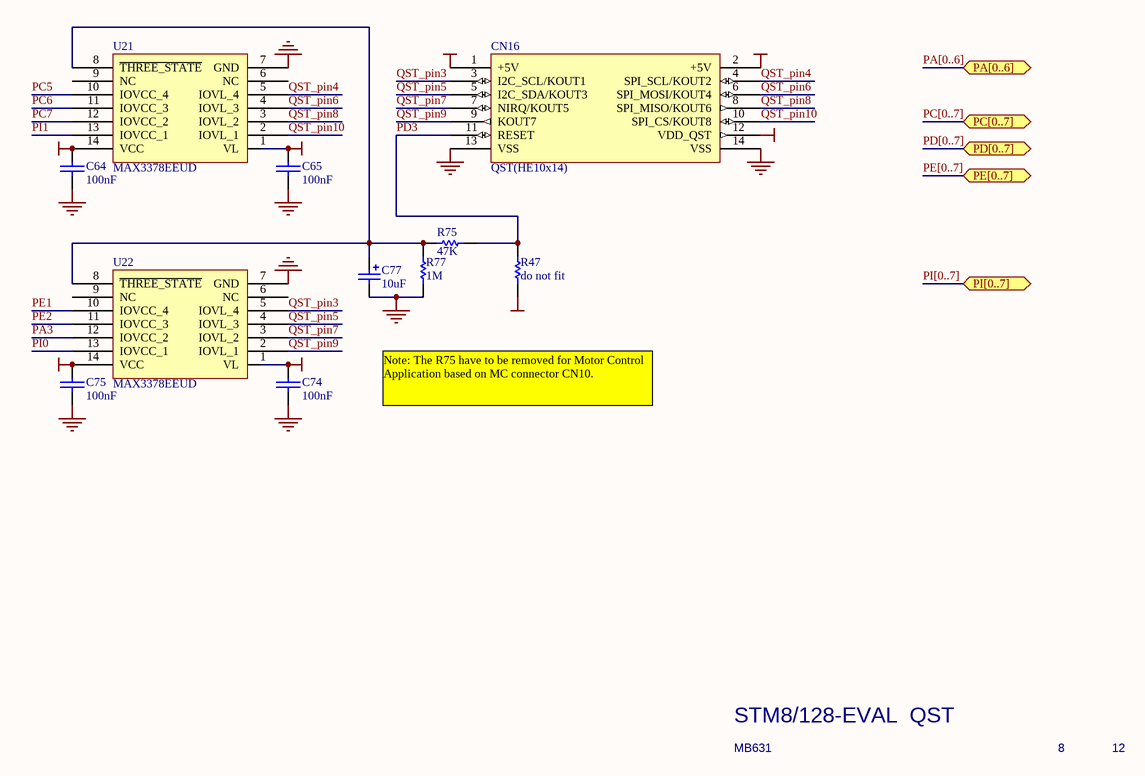
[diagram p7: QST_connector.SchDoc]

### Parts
C64  100nF  [0603P]
C65  100nF  [0603P]
C74  100nF  [0603P]
C75  100nF  [0603P]
C77  10uF  [C160M]
CN16  QST(HE10x14)
R47  do not fit  [0603]
R75  47K  [0603]
R77  1M  [0603]
U21  MAX3378EEUD  [TSSOP14]
U22  MAX3378EEUD  [TSSOP14]

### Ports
PA[0..6] (bidir), PC[0..7] (bidir), PD[0..7] (bidir), PE[0..7] (bidir), PI[0..7] (bidir)

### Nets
+5V: C64.2 C75.2 CN16.1(+5V) CN16.2(+5V) U21.14(VCC) U22.14(VCC)
GND: C64.1 C65.1 C74.1 C75.1 C77.2 CN16.13(VSS) CN16.14(VSS) R77.2 U21.7(GND) U22.7(GND)
VDD_QST: C65.2 C74.2 CN16.12(VDD_QST) R47.2 U21.1(VL) U22.1(VL)
PA3: U22.12(IOVCC_2)
PC5: U21.10(IOVCC_4)
PC6: U21.11(IOVCC_3)
PC7: U21.12(IOVCC_2)
PD3: CN16.11(RESET) R47.1 R75.2
PE1: U22.10(IOVCC_4)
PE2: U22.11(IOVCC_3)
PI0: U22.13(IOVCC_1)
PI1: U21.13(IOVCC_1)
QST_pin3: CN16.3(I2C_SCL/KOUT1) U22.5(IOVL_4)
QST_pin4: CN16.4(SPI_SCL/KOUT2) U21.5(IOVL_4)
QST_pin5: CN16.5(I2C_SDA/KOUT3) U22.4(IOVL_3)
QST_pin6: CN16.6(SPI_MOSI/KOUT4) U21.4(IOVL_3)
QST_pin7: CN16.7(NIRQ/KOUT5) U22.3(IOVL_2)
QST_pin8: CN16.8(SPI_MISO/KOUT6) U21.3(IOVL_2)
QST_pin9: CN16.9(KOUT7) U22.2(IOVL_1)
QST_pin10: CN16.10(SPI_CS/KOUT8) U21.2(IOVL_1)
NetC77_1: C77.1 R75.1 R77.1 U21.8(~{THREE_STATE}) U22.8(~{THREE_STATE})

Not connected (* = marked no-connect by the designer): U21 6(NC) 9(NC); U22 6(NC) 9(NC)

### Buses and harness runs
bus PA[0..6] = port PA[0..6]
bus PC[0..7] = port PC[0..7]
bus PD[0..7] = port PD[0..7]
bus PE[0..7] = port PE[0..7]
bus PI[0..7] = port PI[0..7]

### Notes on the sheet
- Note: The R75 have to be removed for Motor Control Application based on MC connector CN10.
- STM8/128-EVAL  QST
- MB631
- 8
- 12

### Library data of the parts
C64 C65 C74 C75 = CAP
C77 = Cap Pol1: as C8 on sheet Power
CN16 = QST connector
R47 R75 R77 = Res1: Resistor; Value: 1K

## Sheet LIN.SchDoc
size A4; Revision: D.2(PCB.SCH)
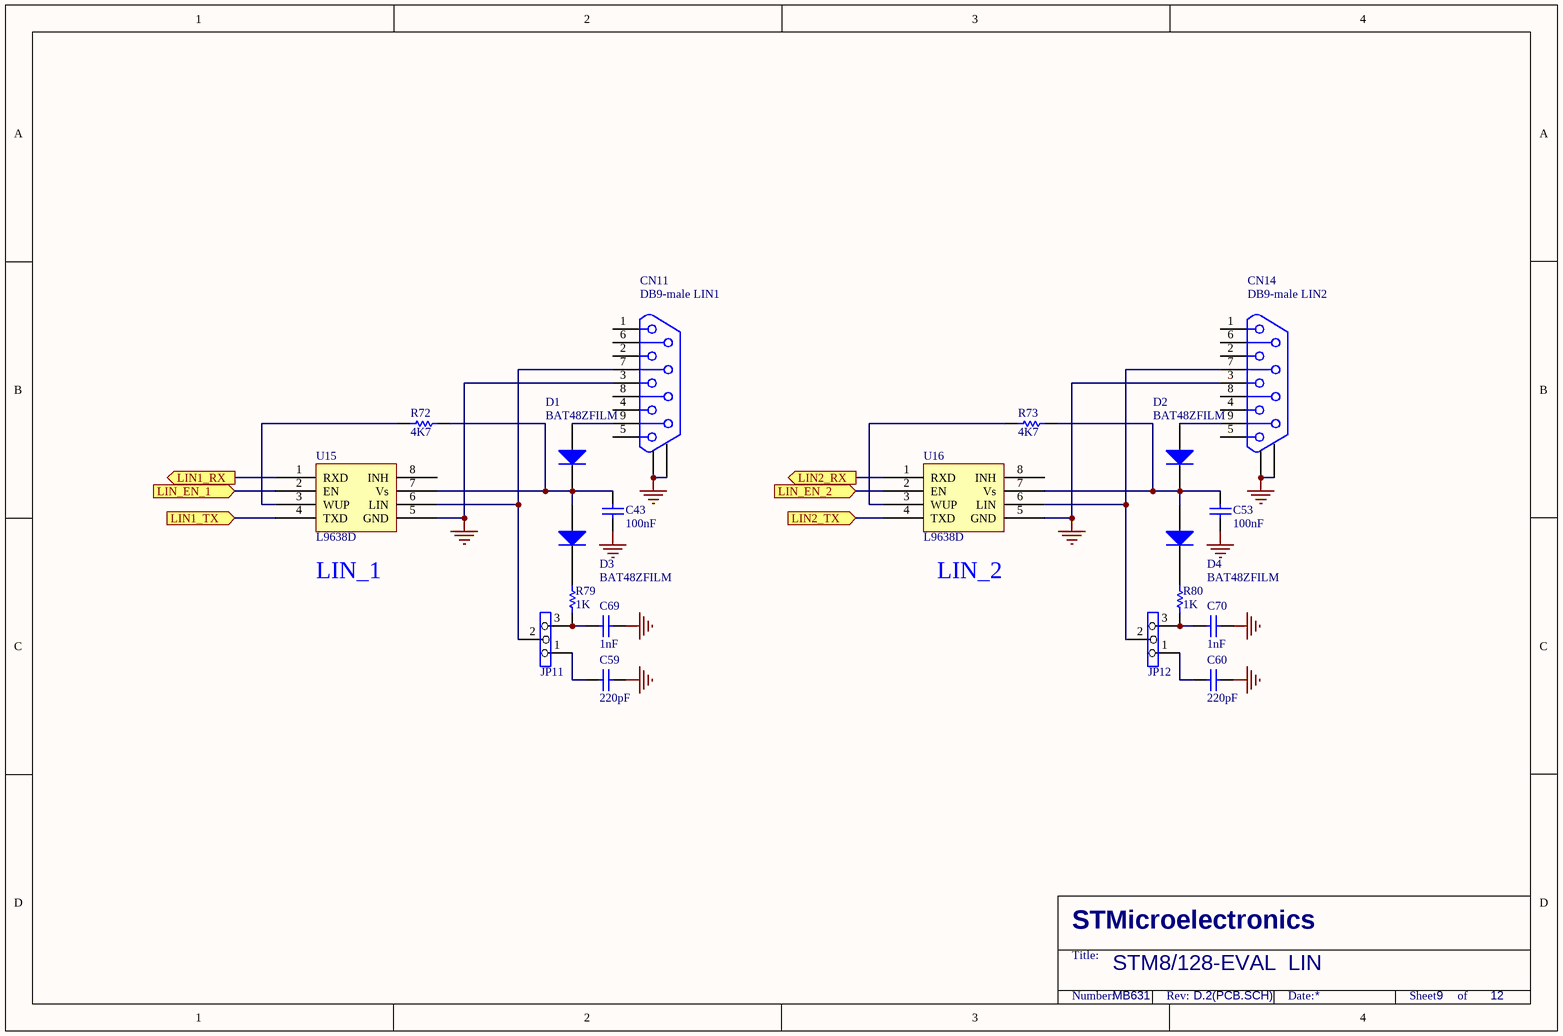
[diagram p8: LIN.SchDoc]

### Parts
C43  100nF  [0603P]
C53  100nF  [0603P]
C59  220pF  [0603P]
C60  220pF  [0603P]
C69  1nF  [0603P]
C70  1nF  [0603P]
CN11  DB9-male LIN1  [DB9/M]
CN14  DB9-male LIN2  [DB9/M]
D1  BAT48ZFILM  [DSO-C2/X3.3]
D2  BAT48ZFILM  [DSO-C2/X3.3]
D3  BAT48ZFILM  [DSO-C2/X3.3]
D4  BAT48ZFILM  [DSO-C2/X3.3]
JP11  (no value)  [SIP3]
JP12  (no value)  [SIP3]
R72  4K7  [0603]
R73  4K7  [0603]
R79  1K  [0805]
R80  1K  [0805]
U15  L9638D  [SO8]
U16  L9638D  [SO8]

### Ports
LIN1_RX (out), LIN1_TX (in), LIN2_RX (out), LIN2_TX (in), LIN_EN_1 (in), LIN_EN_2 (in)

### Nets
GND: C43.2 C53.2 C59.1 C60.1 C69.1 C70.1 CN11.0 CN11.3 CN14.0 CN14.3 U15.5(GND) U16.5(GND)
PF7: U15.2(EN) ; port LIN_EN_1
PG3: U16.2(EN) ; port LIN_EN_2
NetC43_1: C43.1 D1.2(K) D3.1(A) R72.2 U15.7(Vs)
NetC53_1: C53.1 D2.2(K) D4.1(A) R73.2 U16.7(Vs)
NetC59_2: C59.2 JP11.1
NetC60_2: C60.2 JP12.1
NetC69_2: C69.2 JP11.3 R79.2
NetC70_2: C70.2 JP12.3 R80.2
NetCN11_7: CN11.7 JP11.2 U15.6(LIN)
NetCN11_9: CN11.9 D1.1(A)
NetCN14_7: CN14.7 JP12.2 U16.6(LIN)
NetCN14_9: CN14.9 D2.1(A)
NetD3_2: D3.2(K) R79.1
NetD4_2: D4.2(K) R80.1
NetR72_1: R72.1 U15.3(WUP)
NetR73_1: R73.1 U16.3(WUP)
NetU15_1: U15.1(RXD) ; port LIN1_RX
NetU15_4: U15.4(TXD) ; port LIN1_TX
NetU16_1: U16.1(RXD) ; port LIN2_RX
NetU16_4: U16.4(TXD) ; port LIN2_TX

Not connected (* = marked no-connect by the designer): CN11 1 2 4 5 6 8; CN14 1 2 4 5 6 8; U15 8(INH); U16 8(INH)

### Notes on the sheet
- (near U15) LIN_1
- (near U16) LIN_2
- STM8/128-EVAL  LIN
- MB631
- 9
- 12

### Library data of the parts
C43 C53 = CAP: Capacitor
C59 C60 C69 C70 = CAP: Capacitor; Value: 100nF
CN11 CN14 = DB9
D1-D4 = Diode: Default Diode; Code - JEDEC: DO-214-AB
JP11 JP12 = Jumper3
R72 R73 = res1: Resistor; Value: 1K
R79 R80 = Res1: Resistor

## Sheet UART_IrDA.SchDoc
size A4; Revision: D.2(PCB.SCH)
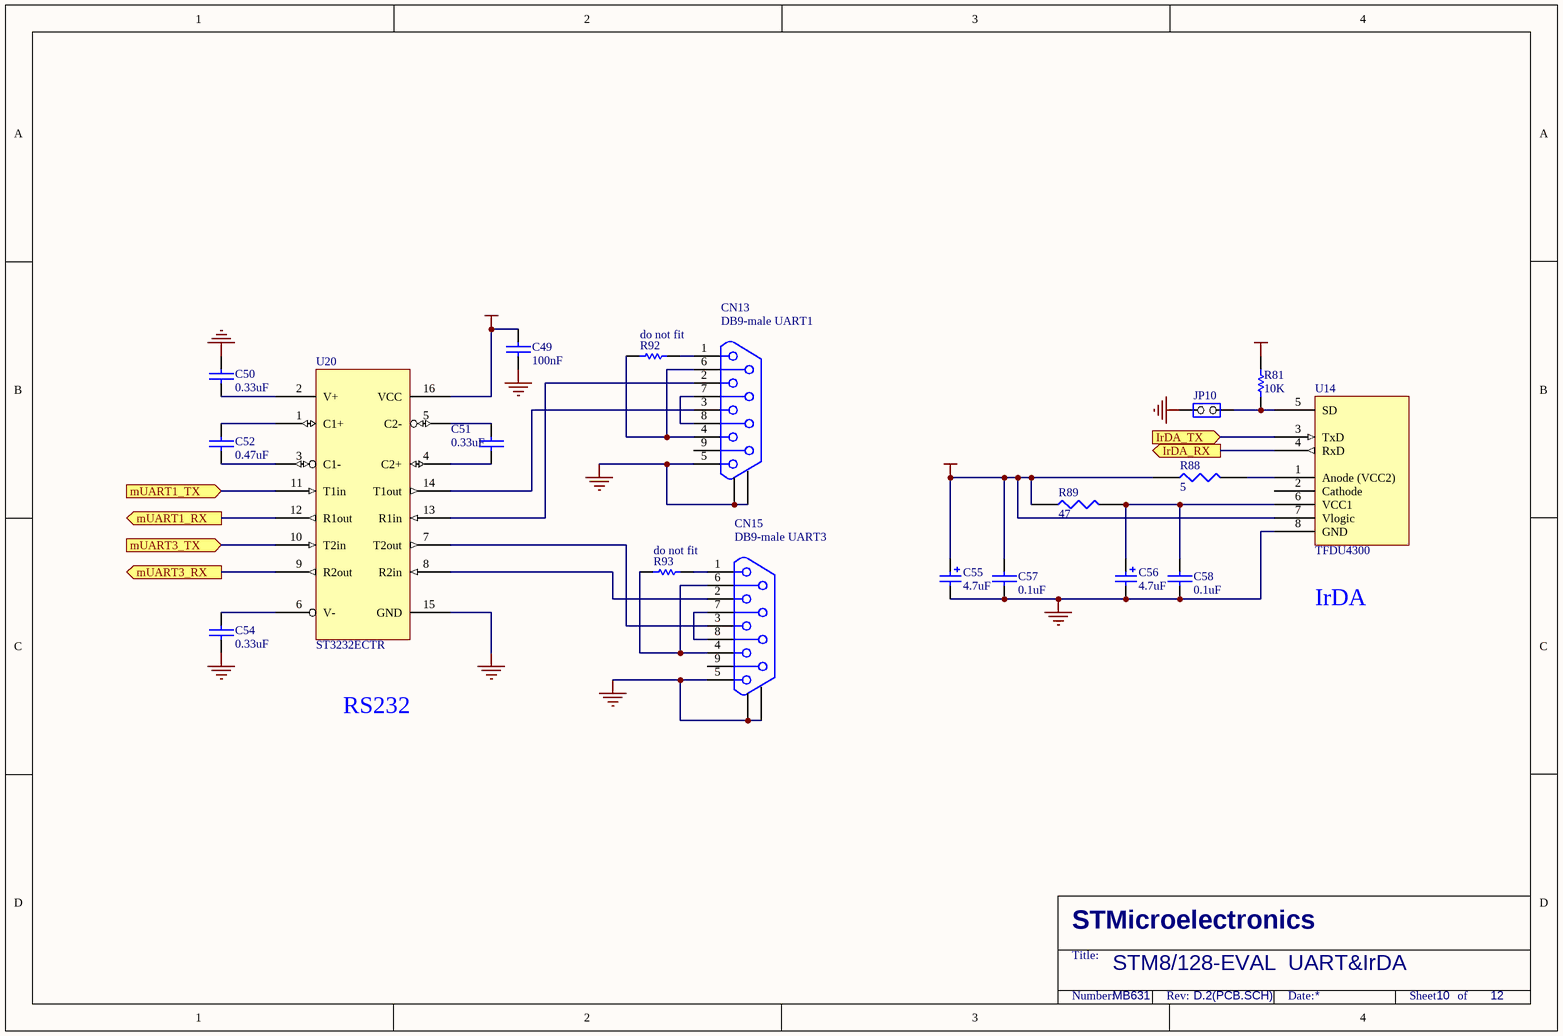
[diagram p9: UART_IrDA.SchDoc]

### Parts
C49  100nF  [0603P]
C50  0.33uF  [0603P]
C51  0.33uF  [0603P]
C52  0.47uF  [0603P]
C54  0.33uF  [0603P]
C55  4.7uF  [TAN-B]
C56  4.7uF  [TAN-B]
C57  0.1uF  [0603P]
C58  0.1uF  [0603P]
CN13  DB9-male UART1  [DB9/M]
CN15  DB9-male UART3  [DB9/M]
JP10  (no value)  [SIP2]
R81  10K  [0603]
R88  5  [0603]
R89  47  [0603]
R92  do not fit  [0603_NC]
R93  do not fit  [0603_NC]
U14  TFDU4300  [IR_VISHAY3]
U20  ST3232ECTR  [TSSOP16]

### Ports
IrDA_RX (out), IrDA_TX (in), mUART1_RX (out), mUART1_TX (in), mUART3_RX (out), mUART3_TX (in)

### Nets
+5V: C49.1 C55.1 C57.1 R81.2 R88.1 R89.1 U14.7(Vlogic) U20.16(VCC)
GND: C49.2 C50.1 C54.1 C55.2 C56.2 C57.2 C58.2 CN13.0 CN13.5 CN15.0 CN15.5 JP10.2(NO) U14.8(GND) U20.15(GND)
NetC50_2: C50.2 U20.2(V+)
NetC51_1: C51.1 U20.4(C2+)
NetC51_2: C51.2 U20.5(C2-)
NetC52_1: C52.1 U20.1(C1+)
NetC52_2: C52.2 U20.3(C1-)
NetC54_2: C54.2 U20.6(V-)
NetC56_1: C56.1 C58.1 R89.2 U14.6(VCC1)
NetCN13_1: CN13.1 R92.2
NetCN13_2: CN13.2 U20.13(R1in)
NetCN13_3: CN13.3 U20.14(T1out)
NetCN13_4: CN13.4 CN13.6 R92.1
NetCN13_7: CN13.7 CN13.8
NetCN15_1: CN15.1 R93.2
NetCN15_2: CN15.2 U20.8(R2in)
NetCN15_3: CN15.3 U20.7(T2out)
NetCN15_4: CN15.4 CN15.6 R93.1
NetCN15_7: CN15.7 CN15.8
NetJP10_1: JP10.1(COMMON) R81.1 U14.5(SD)
NetR88_2: R88.2 U14.1(Anode_(VCC2))
NetU14_3: U14.3(TxD) ; port IrDA_TX
NetU14_4: U14.4(RxD) ; port IrDA_RX
NetU17_4: U20.12(R1out) ; port mUART1_RX
NetU17_11: U20.11(T1in) ; port mUART1_TX
NetU18_5: U20.9(R2out) ; port mUART3_RX
NetU18_14: U20.10(T2in) ; port mUART3_TX

Not connected (* = marked no-connect by the designer): CN13 9; CN15 9; U14 2(Cathode)

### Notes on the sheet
- IrDA
- RS232
- STM8/128-EVAL  UART&IrDA
- MB631
- 10
- 12

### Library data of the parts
C49-C52 C54 C57 C58 = CAP: Capacitor
C55 C56 = Cap Pol1: as C6 on sheet MCU
CN13 CN15 = DB9
JP10 = JP2
R81 = Res1: Resistor; Value: 1K
R88 R89 = RES1
R92 R93 = res1: Resistor; Value: 1K
U20 = ST3232: 3.3V/5V Dual RS232 Transceiver w/ Int. Cap.

## Sheet UART_LIN_IrDA_SmartCard.SchDoc
size A4; Revision: D.2(PCB.SCH)
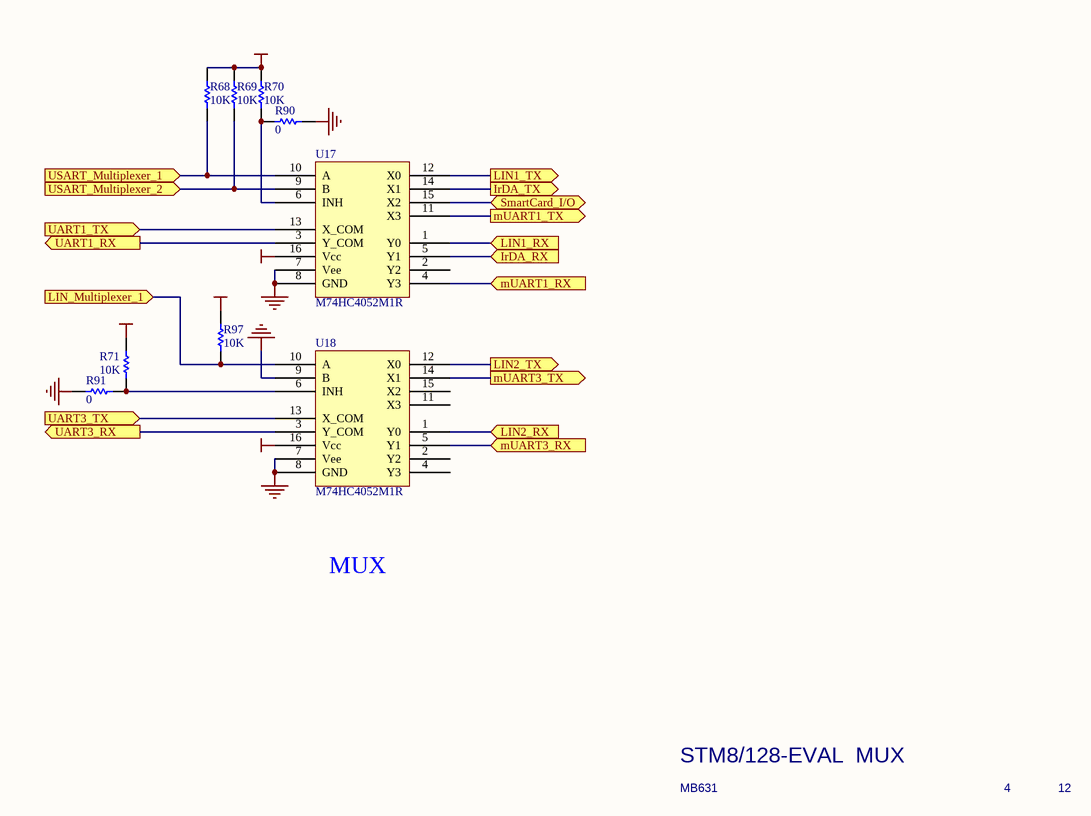
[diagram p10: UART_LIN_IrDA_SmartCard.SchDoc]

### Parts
R68  10K  [0603]
R69  10K  [0603]
R70  10K  [0603]
R71  10K  [0603]
R90  0  [0805]
R91  0  [0805]
R97  10K  [0603]
U17  M74HC4052M1R  [SO16]
U18  M74HC4052M1R  [SO16]

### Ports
IrDA_RX (in), IrDA_TX (out), LIN1_RX (in), LIN1_TX (out), LIN2_RX (in), LIN2_TX (out), LIN_Multiplexer_1 (in), mUART1_RX (in), mUART1_TX (out), mUART3_RX (in), mUART3_TX (out), SmartCard_I/O (bidir), UART1_RX (out), UART1_TX (in), UART3_RX (out), UART3_TX (in), USART_Multiplexer_1 (in), USART_Multiplexer_2 (in)

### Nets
+5V: R68.1 R69.1 R70.1 R71.1 R97.1 U17.16(Vcc) U18.16(Vcc)
GND: R90.2 R91.1 U17.7(Vee) U17.8(GND) U18.7(Vee) U18.8(GND) U18.9(B)
PA4: U17.3(Y_COM) ; port UART1_RX
PA5: U17.13(X_COM) ; port UART1_TX
PD5: U18.13(X_COM) ; port UART3_TX
PD6: U18.3(Y_COM) ; port UART3_RX
PF5: R68.2 U17.10(A) ; port USART_Multiplexer_1
PF6: R69.2 U17.9(B) ; port USART_Multiplexer_2
PG6: R97.2 U18.10(A) ; port LIN_Multiplexer_1
NetR70_2: R70.2 R90.1 U17.6(INH)
NetR71_2: R71.2 R91.2 U18.6(INH)
NetU14_3: U17.14(X1) ; port IrDA_TX
NetU14_4: U17.5(Y1) ; port IrDA_RX
NetU15_1: U17.1(Y0) ; port LIN1_RX
NetU15_4: U17.12(X0) ; port LIN1_TX
NetU16_1: U18.1(Y0) ; port LIN2_RX
NetU16_4: U18.12(X0) ; port LIN2_TX
NetU17_4: U17.4(Y3) ; port mUART1_RX
NetU17_11: U17.11(X3) ; port mUART1_TX
NetU17_15: U17.15(X2) ; port SmartCard_I/O
NetU18_5: U18.5(Y1) ; port mUART3_RX
NetU18_14: U18.14(X1) ; port mUART3_TX

Not connected (* = marked no-connect by the designer): U17 2(Y2); U18 2(Y2) 4(Y3) 11(X3) 15(X2)

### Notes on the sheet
- MUX
- STM8/128-EVAL  MUX
- MB631
- 4
- 12

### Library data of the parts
R68-R71 R90 R91 R97 = res1: Resistor; Value: 1K

## Sheet SmartCard.SchDoc
size A4; Revision: D.2(PCB.SCH)
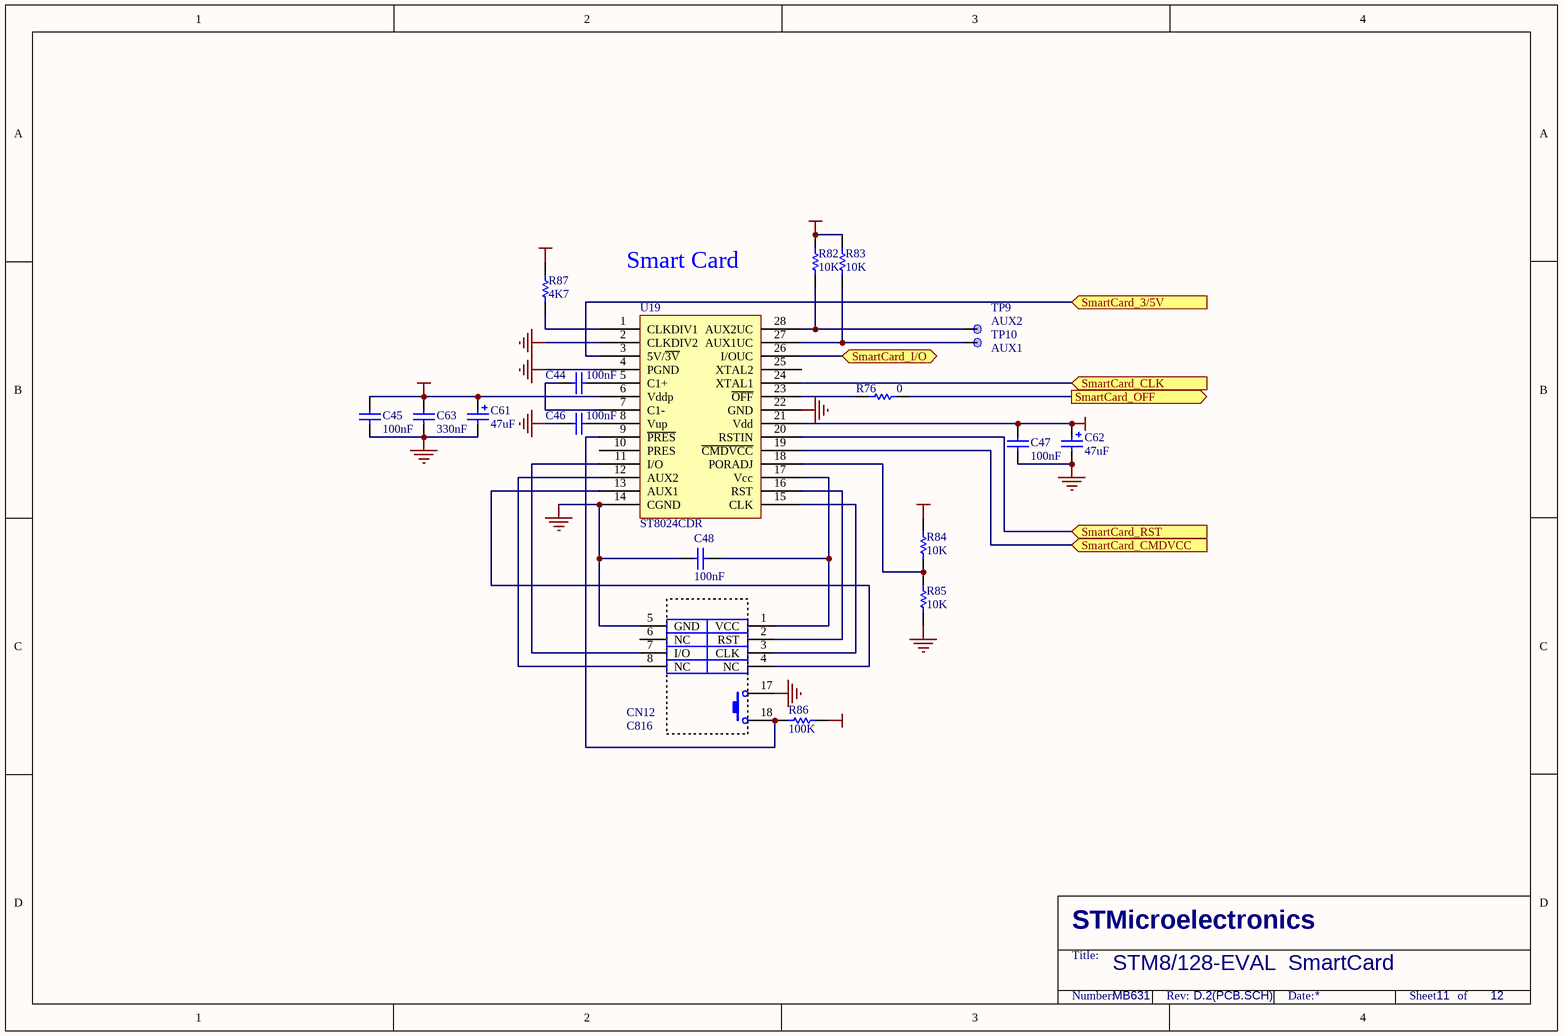
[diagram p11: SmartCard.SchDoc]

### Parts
C44  100nF  [0603P]
C45  100nF  [0603P]
C46  100nF  [0603P]
C47  100nF  [0603P]
C48  100nF  [0603P]
C61  47uF  [TAN-B]
C62  47uF  [TAN-B]
C63  330nF  [0603]
CN12  C816  [SAM(C816)]
R76  0  [0805]
R82  10K  [0603]
R83  10K  [0603]
R84  10K  [0603]
R85  10K  [0603]
R86  100K  [0603]
R87  4K7  [0603]
TP9  AUX2  [TP]
TP10  AUX1  [TP]
U19  ST8024CDR  [SO28]

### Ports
SmartCard_3/5V (in), SmartCard_CLK (in), SmartCard_CMDVCC (in), SmartCard_I/O (bidir), SmartCard_OFF (out), SmartCard_RST (in)

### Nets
+5V: C45.1 C47.1 C61.1 C62.1 C63.1 R82.1 R83.1 R84.1 R86.1 R87.1 U19.6(Vddp) U19.21(Vdd)
GND: C45.2 C46.2 C47.2 C48.1 C61.2 C62.2 C63.2 CN12.5(GND) CN12.17 R85.2 U19.2(CLKDIV2) U19.4(PGND) U19.14(CGND) U19.22(GND)
PA6: U19.24(XTAL1) ; port SmartCard_CLK
PE0: R76.1 ; port SmartCard_OFF
PG4: U19.3(5V/~{3V}) ; port SmartCard_3/5V
PG5: U19.20(RSTIN) ; port SmartCard_RST
PG7: U19.19(~{CMDVCC}) ; port SmartCard_CMDVCC
NetC44_1: C44.1 U19.7(C1-)
NetC44_2: C44.2 U19.5(C1+)
NetC46_1: C46.1 U19.8(Vup)
NetC48_2: C48.2 CN12.1(VCC) U19.17(Vcc)
NetCN12_2: CN12.2(RST) U19.16(RST)
NetCN12_3: CN12.3(CLK) U19.15(CLK)
NetCN12_4: CN12.4(NC) U19.13(AUX1)
NetCN12_7: CN12.7(I/O) U19.11(I/O)
NetCN12_8: CN12.8(NC) U19.12(AUX2)
NetCN12_18: CN12.18 R86.2 U19.9(~{PRES})
NetR76_2: R76.2 U19.23(~{OFF})
NetR82_2: R82.2 TP9.1 U19.28(AUX2UC)
NetR83_2: R83.2 TP10.1 U19.27(AUX1UC)
NetR84_2: R84.2 R85.1 U19.18(PORADJ)
NetR87_2: R87.2 U19.1(CLKDIV1)
NetU17_15: U19.26(I/OUC) ; port SmartCard_I/O

Not connected (* = marked no-connect by the designer): CN12 6(NC); U19 10(PRES) 25(XTAL2)

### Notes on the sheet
- Smart Card
- STM8/128-EVAL  SmartCard
- MB631
- 11
- 12

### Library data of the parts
C44-C48 = CAP: Capacitor
C61 C62 = Cap Pol1: as C6 on sheet MCU
C63 = CAP: Capacitor; Value: 100nF
CN12 = Smart_card_CN
R76 R82-R87 = Res1: Resistor; Value: 1K
TP9 TP10 = TP
U19 = ST8024CTR

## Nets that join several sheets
+3V3: MotorCtrl (CN10.28), JOY_LCD_SDcard_CAN_EEPROM (6 pins), Power (6 pins), STice_ExConnector (CN1.48)
+5V: MCU (14 pins), Audio (7 pins), MotorCtrl (CN10.25 R67.2), JOY_LCD_SDcard_CAN_EEPROM (20 pins), Power (6 pins), QST_connector (6 pins), UART_IrDA (8 pins), UART_LIN_IrDA_SmartCard (7 pins), SmartCard (12 pins)
+5V_MCU: MCU (8 pins), STice_ExConnector (CN2.7 CN2.8 CN2.49)
+5V_VDDA: MCU (5 pins), STice_ExConnector (CN2.23)
D5V: Power (JP3.1), STice_ExConnector (CN1.49 CN5.19)
GND: MCU (40 pins), Audio (13 pins), MotorCtrl (27 pins), JOY_LCD_SDcard_CAN_EEPROM (28 pins), Power (15 pins), STice_ExConnector (19 pins), QST_connector (10 pins), LIN (12 pins), UART_IrDA (14 pins), UART_LIN_IrDA_SmartCard (7 pins), SmartCard (14 pins)
NetC39_2: MCU (JP13.1), MotorCtrl (C39.2 CN10.29)
NetCN9_10: MCU (R101.1), JOY_LCD_SDcard_CAN_EEPROM (CN9.10 R100.1)
NetCN10_23: MCU (JP13.3), MotorCtrl (CN10.23)
NetU14_3: UART_IrDA (U14.3), UART_LIN_IrDA_SmartCard (U17.14)
NetU14_4: UART_IrDA (U14.4), UART_LIN_IrDA_SmartCard (U17.5)
NetU15_1: LIN (U15.1), UART_LIN_IrDA_SmartCard (U17.1)
NetU15_4: LIN (U15.4), UART_LIN_IrDA_SmartCard (U17.12)
NetU16_1: LIN (U16.1), UART_LIN_IrDA_SmartCard (U18.1)
NetU16_4: LIN (U16.4), UART_LIN_IrDA_SmartCard (U18.12)
NetU17_4: UART_IrDA (U20.12), UART_LIN_IrDA_SmartCard (U17.4)
NetU17_11: UART_IrDA (U20.11), UART_LIN_IrDA_SmartCard (U17.11)
NetU17_15: UART_LIN_IrDA_SmartCard (U17.15), SmartCard (U19.26)
NetU18_5: UART_IrDA (U20.9), UART_LIN_IrDA_SmartCard (U18.5)
NetU18_14: UART_IrDA (U20.10), UART_LIN_IrDA_SmartCard (U18.14)
PA0: MCU (JP1.2 U1.1), STice_ExConnector (CN5.12)
PA1: MCU (C4.1 R2.2 U1.2 X1.2), STice_ExConnector (CN2.2 CN5.14)
PA2: MCU (R98.1 U1.3), STice_ExConnector (CN2.3 CN5.13)
PA3: MCU (U1.9), MotorCtrl (C37.2 CN10.34), STice_ExConnector (CN2.9 CN5.16), QST_connector (U22.12)
PA4: MCU (U1.10), STice_ExConnector (CN2.10 CN5.15), UART_LIN_IrDA_SmartCard (U17.3)
PA5: MCU (U1.11), STice_ExConnector (CN2.11 CN5.18), UART_LIN_IrDA_SmartCard (U17.13)
PA6: MCU (U1.12), STice_ExConnector (CN2.12 CN5.17), SmartCard (U19.24)
PB0: MCU (U1.34), MotorCtrl (C36.2 R65.1), STice_ExConnector (CN2.34 CN5.45)
PB1: MCU (U1.33), MotorCtrl (C35.2 R64.1), STice_ExConnector (CN2.33 CN5.44)
PB2: MCU (U1.32), MotorCtrl (C34.2 R62.1), STice_ExConnector (CN2.32 CN5.43)
PB3: MCU (U1.31), MotorCtrl (C32.2 R61.2 R66.2), STice_ExConnector (CN2.31 CN5.42)
PB4: MCU (U1.30), JOY_LCD_SDcard_CAN_EEPROM (R41.2), STice_ExConnector (CN2.30 CN5.41)
PB5: MCU (U1.29), JOY_LCD_SDcard_CAN_EEPROM (R42.2), STice_ExConnector (CN2.29 CN5.40)
PB6: MCU (U1.28), JOY_LCD_SDcard_CAN_EEPROM (R44.2), STice_ExConnector (CN2.28 CN5.38)
PB7: MCU (U1.27), JOY_LCD_SDcard_CAN_EEPROM (R40.2), STice_ExConnector (CN2.27 CN5.37)
PC0: MCU (R4.1 U1.42), STice_ExConnector (CN1.36 CN2.42)
PC1: MCU (U1.43), MotorCtrl (CN10.3), STice_ExConnector (CN1.33 CN2.43)
PC2: MCU (U1.44), MotorCtrl (CN10.7), STice_ExConnector (CN1.34 CN2.44)
PC3: MCU (U1.45), MotorCtrl (CN10.11), STice_ExConnector (CN1.29 CN2.45)
PC4: MCU (U1.46), Audio (R30.1), STice_ExConnector (CN1.27 CN2.46)
PC5: MCU (U1.47), JOY_LCD_SDcard_CAN_EEPROM (U11.11 U13.4), STice_ExConnector (CN1.28 CN2.47), QST_connector (U21.10)
PC6: MCU (U1.50), JOY_LCD_SDcard_CAN_EEPROM (U11.12 U13.5), STice_ExConnector (CN1.25 CN2.50), QST_connector (U21.11)
PC7: MCU (U1.51), JOY_LCD_SDcard_CAN_EEPROM (U11.10), STice_ExConnector (CN1.26 CN2.51), QST_connector (U21.12)
PD0: MCU (JP13.2 U1.73), STice_ExConnector (CN2.75 CN5.2)
PD1: MCU (CN4.2 CN17.2 U1.74), STice_ExConnector (CN2.78 CN5.3)
PD2: MCU (U1.75), MotorCtrl (C41.2 CN10.27 R45.2), STice_ExConnector (CN2.77 CN5.4)
PD3: MCU (U1.76), MotorCtrl (C38.2 CN10.31 JP9.1), STice_ExConnector (CN2.80 CN5.5), QST_connector (CN16.11 R47.1 R75.2)
PD4: MCU (U1.77), Audio (JP14.3 TP15.1), MotorCtrl (C40.2 CN10.33), STice_ExConnector (CN2.79 CN5.6)
PD5: MCU (U1.78), STice_ExConnector (CN2.82 CN5.7), UART_LIN_IrDA_SmartCard (U18.13)
PD6: MCU (U1.79), STice_ExConnector (CN2.81 CN5.8), UART_LIN_IrDA_SmartCard (U18.3)
PD7: MCU (U1.80), JOY_LCD_SDcard_CAN_EEPROM (R39.2), STice_ExConnector (CN2.84 CN5.9)
PE0: MCU (U1.70), STice_ExConnector (CN1.4 CN2.74), SmartCard (R76.1)
PE1: MCU (U1.69), JOY_LCD_SDcard_CAN_EEPROM (R95.1), STice_ExConnector (CN1.5 CN2.71), QST_connector (U22.10)
PE2: MCU (U1.68), JOY_LCD_SDcard_CAN_EEPROM (R96.1), STice_ExConnector (CN1.6 CN2.72), QST_connector (U22.11)
PE3: MCU (U1.67), MotorCtrl (R60.2), STice_ExConnector (CN1.7 CN2.69)
PE4: MCU (R101.2 U1.66), STice_ExConnector (CN1.8 CN2.70)
PE5: MCU (U1.41), JOY_LCD_SDcard_CAN_EEPROM (U11.13), STice_ExConnector (CN1.35 CN2.41)
PE6: MCU (R5.1 U1.40), STice_ExConnector (CN1.38 CN2.40)
PE7: MCU (U1.39), MotorCtrl (C33.2 R63.2), STice_ExConnector (CN1.37 CN2.39)
PF0: MCU (U1.26), JOY_LCD_SDcard_CAN_EEPROM (U13.6), STice_ExConnector (CN2.26 CN5.36)
PF1: MCU (R46.2 U1.25), STice_ExConnector (CN2.25 CN5.35)
PF2: MCU (R74.1 U1.22), STice_ExConnector (CN2.22 CN5.34)
PF3: MCU (U1.21), Audio (R21.1), STice_ExConnector (CN2.21 CN5.33)
PF4: MCU (CN3.5 U1.20), STice_ExConnector (CN2.20 CN5.32)
PF5: MCU (U1.19), STice_ExConnector (CN2.19 CN5.31), UART_LIN_IrDA_SmartCard (R68.2 U17.10)
PF6: MCU (U1.18), STice_ExConnector (CN2.18 CN5.29), UART_LIN_IrDA_SmartCard (R69.2 U17.9)
PF7: MCU (U1.17), STice_ExConnector (CN2.17 CN5.28), LIN (U15.2)
PG0: MCU (U1.52), JOY_LCD_SDcard_CAN_EEPROM (U10.1), STice_ExConnector (CN1.23 CN2.52)
PG1: MCU (U1.53), JOY_LCD_SDcard_CAN_EEPROM (R43.2), STice_ExConnector (CN1.24 CN2.53)
PG2: MCU (U1.54), MotorCtrl (CN10.21), STice_ExConnector (CN1.21 CN2.54)
PG3: MCU (U1.55), STice_ExConnector (CN1.22 CN2.55), LIN (U16.2)
PG4: MCU (U1.56), STice_ExConnector (CN1.20 CN2.56), SmartCard (U19.3)
PG5: MCU (U1.63), STice_ExConnector (CN1.11 CN2.65), SmartCard (U19.20)
PG6: MCU (U1.64), STice_ExConnector (CN1.12 CN2.68), UART_LIN_IrDA_SmartCard (R97.2 U18.10)
PG7: MCU (U1.65), STice_ExConnector (CN1.9 CN2.67), SmartCard (U19.19)
PH0: MCU (R12.2 U1.13), STice_ExConnector (CN2.13 CN5.22)
PH1: MCU (R13.2 U1.14), STice_ExConnector (CN2.14 CN5.25)
PH2: MCU (R14.2 U1.15), STice_ExConnector (CN2.15 CN5.26)
PH3: MCU (R15.2 U1.16), STice_ExConnector (CN2.16 CN5.27)
PH4: MCU (U1.35), JOY_LCD_SDcard_CAN_EEPROM (R103.2 R107.2), STice_ExConnector (CN1.44 CN2.35)
PH5: MCU (U1.36), MotorCtrl (CN10.13), STice_ExConnector (CN1.41 CN2.36)
PH6: MCU (U1.37), MotorCtrl (CN10.9), STice_ExConnector (CN1.42 CN2.37)
PH7: MCU (U1.38), MotorCtrl (CN10.5), STice_ExConnector (CN1.40 CN2.38)
PI0: MCU (R7.2 U1.57), STice_ExConnector (CN1.17 CN2.57), QST_connector (U22.13)
PI1: MCU (R8.2 U1.58), STice_ExConnector (CN1.18 CN2.62), QST_connector (U21.13)
PI2: MCU (R9.2 U1.59), STice_ExConnector (CN1.15 CN2.61)
PI3: MCU (R10.2 U1.60), STice_ExConnector (CN1.16 CN2.64)
PI4: MCU (R58.2 U1.61), STice_ExConnector (CN1.13 CN2.63)
PI5: MCU (R59.2 U1.62), STice_ExConnector (CN1.14 CN2.66)
PI6: MCU (R99.2 U1.71), STice_ExConnector (CN1.3 CN2.73)
PI7: MCU (R102.2 U1.72), STice_ExConnector (CN1.2 CN2.76)
RESET#: MCU (6 pins), STice_ExConnector (CN2.1 R16.2)
VCAP: MCU (C6.1 U1.6), STice_ExConnector (CN2.6)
